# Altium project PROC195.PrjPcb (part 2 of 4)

## Sheet PROC195_EPWM.SchDoc
size 431 x 279 mm; Date: Not shown in title block; ApprovedBy: Not shown in title block; CheckedBy: Not shown in title block; Author: Not shown in title block; CompanyName: Not shown in title block; Engineer: Not shown in title block; Organization: Not shown in title block; Address1: Not shown in title block; Address2: Not shown in title block; Address3: Not shown in title block; Address4: Not shown in title block; DocumentNumber: 1; Revision: Use project parameter SCH_Rev; SheetNumber: 10; SheetTotal: 20; PageSetup: Record=PageOptions¦CenterHorizontal=True¦CenterVertical=True¦PrintScale=0.97¦XCorrection=1.00¦YCorrection=1.00¦PrintKind=0¦BorderSize=5000000¦LeftOffset=0¦BottomOffset=0¦Orientation=2¦PaperLength=1000¦PaperWidth=1000¦Scale=100¦PaperSource=15¦PrintQuality=600¦MediaType=1¦DitherType=10¦PaperKind=Letter¦PrintScaleMode=1
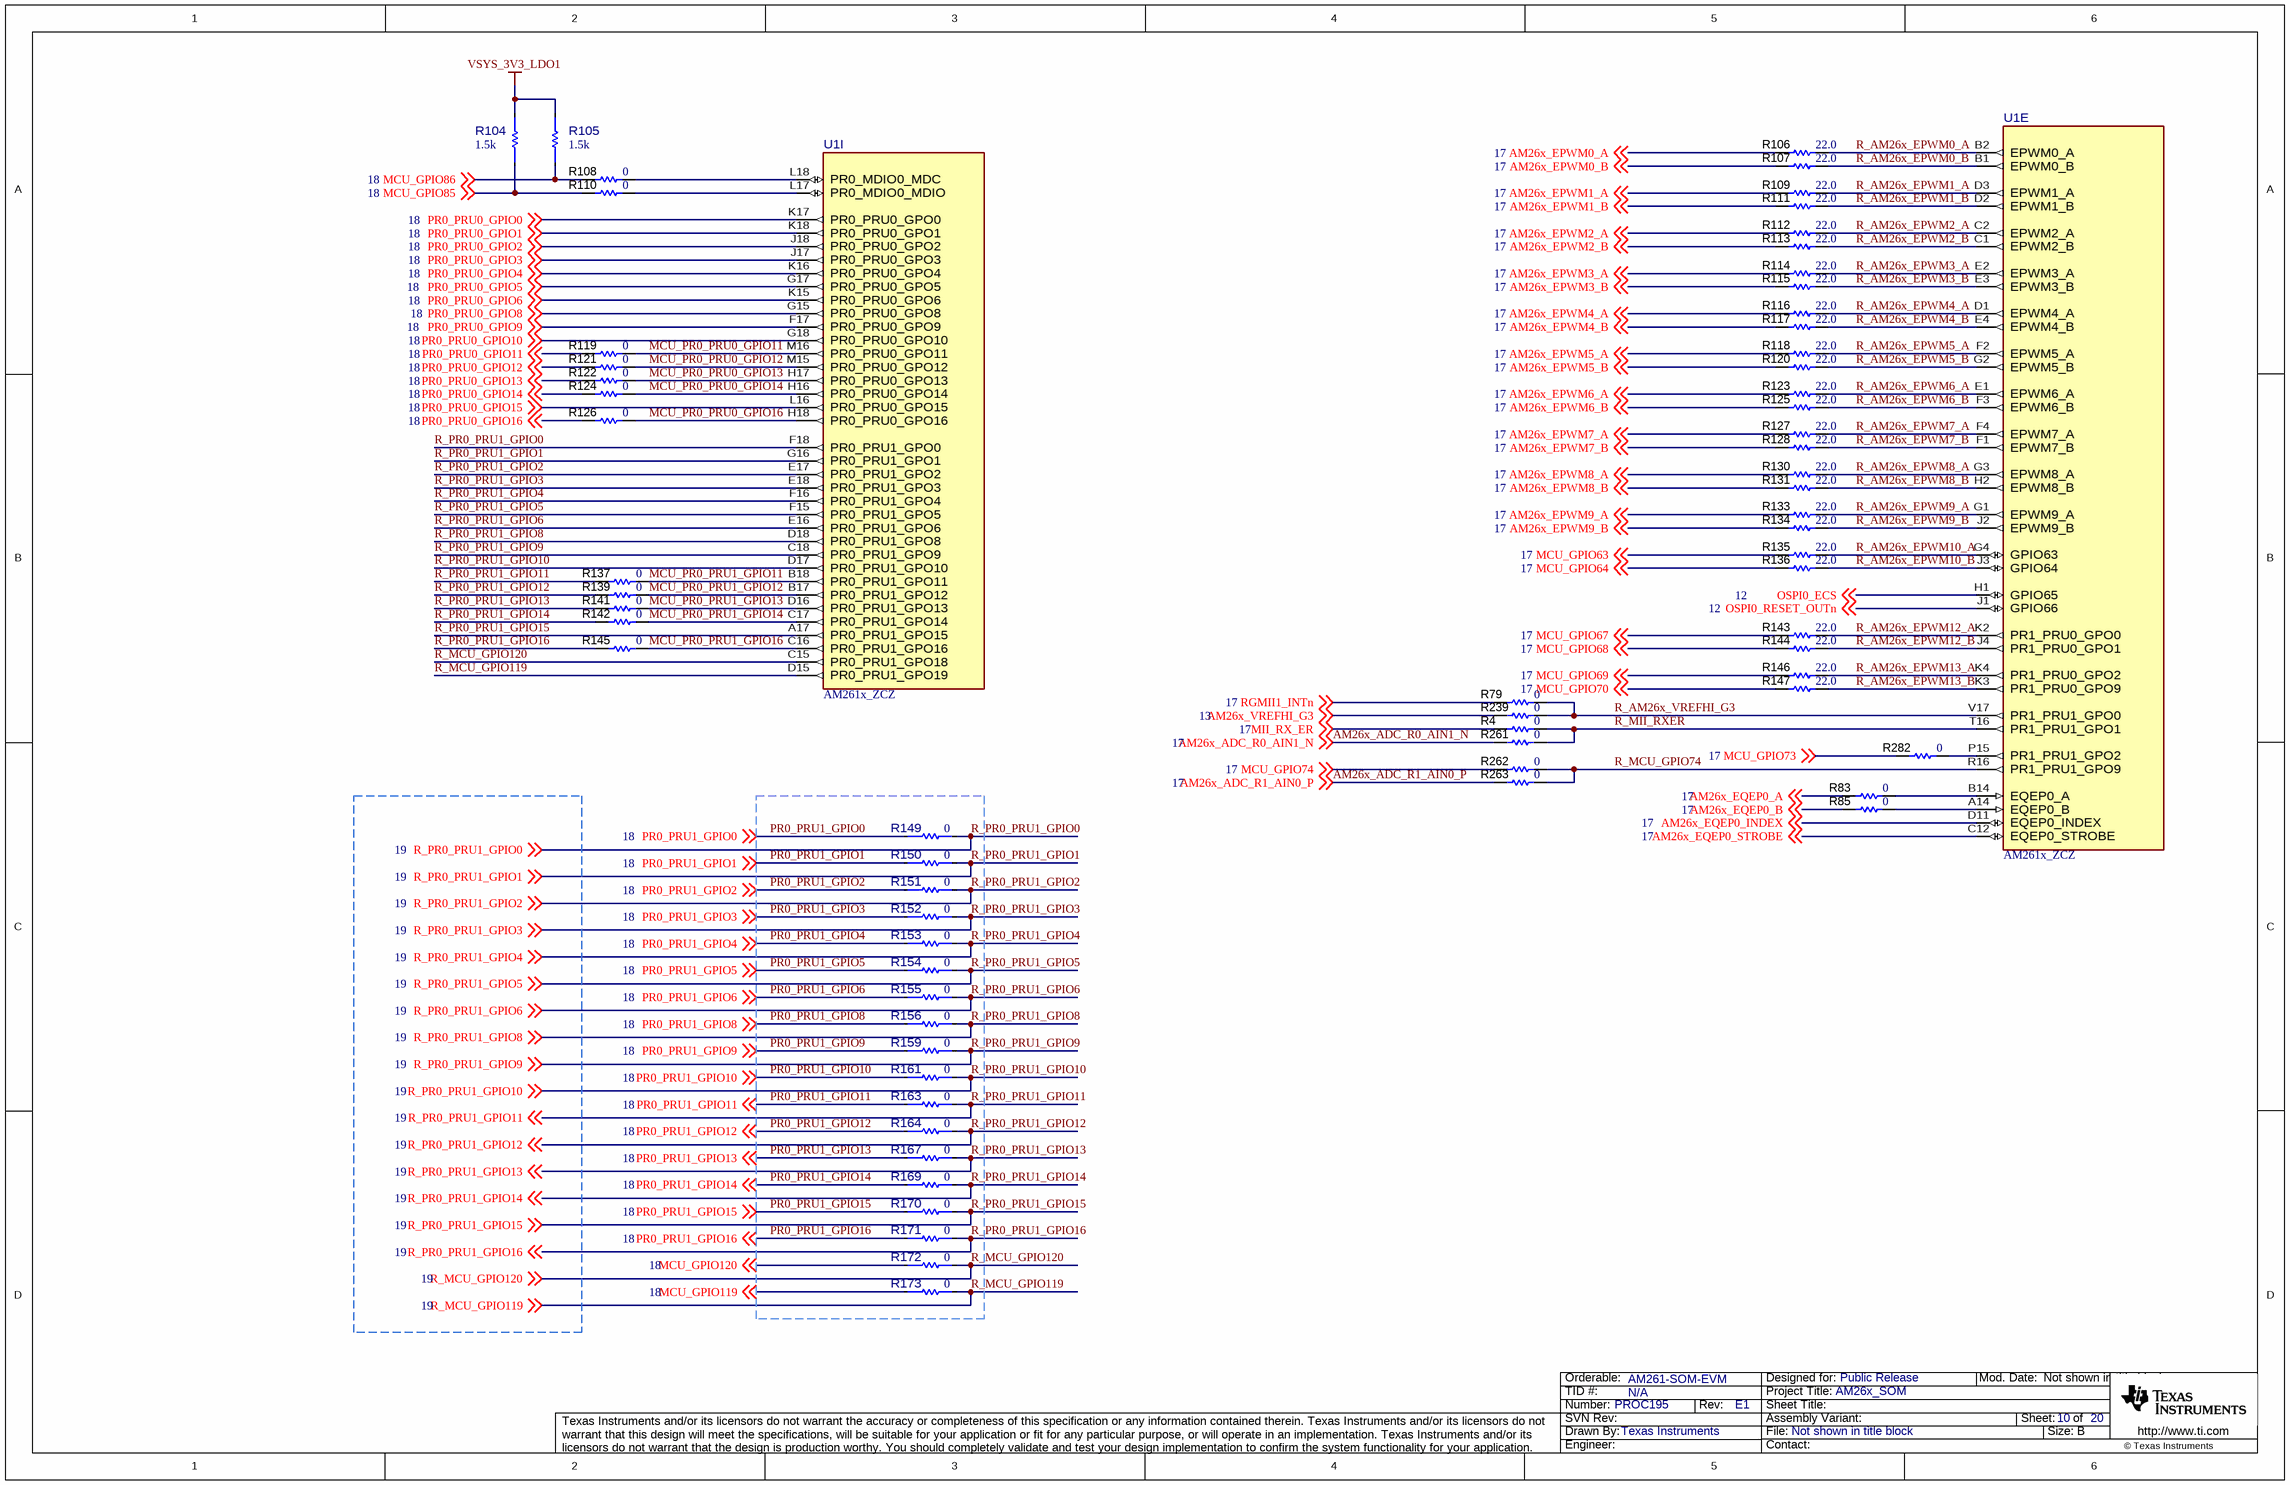
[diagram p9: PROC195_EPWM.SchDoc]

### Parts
R4  ValueDisplayed: 0  [0201]  (hidden comment: ERJ-1GN0R00C)
R79  ValueDisplayed: 0  [0201]  (hidden comment: ERJ-1GN0R00C)
R83  ValueDisplayed: 0  [0201]  (hidden comment: ERJ-1GN0R00C)
R85  ValueDisplayed: 0  [0201]  (hidden comment: ERJ-1GN0R00C)
R104  value 1.5k  [FP-ERJ-2GEJ152X_0402-MFG]  (hidden comment: ERJ-2GEJ152X)
R105  value 1.5k  [FP-ERJ-2GEJ152X_0402-MFG]  (hidden comment: ERJ-2GEJ152X)
R106  ValueDisplayed: 22.0  [0201]  (hidden comment: RC0201FR-0722RL)
R107  ValueDisplayed: 22.0  [0201]  (hidden comment: RC0201FR-0722RL)
R108  ValueDisplayed: 0  [0201]  (hidden comment: ERJ-1GN0R00C)
R109  ValueDisplayed: 22.0  [0201]  (hidden comment: RC0201FR-0722RL)
R110  ValueDisplayed: 0  [0201]  (hidden comment: ERJ-1GN0R00C)
R111  ValueDisplayed: 22.0  [0201]  (hidden comment: RC0201FR-0722RL)
R112  ValueDisplayed: 22.0  [0201]  (hidden comment: RC0201FR-0722RL)
R113  ValueDisplayed: 22.0  [0201]  (hidden comment: RC0201FR-0722RL)
R114  ValueDisplayed: 22.0  [0201]  (hidden comment: RC0201FR-0722RL)
R115  ValueDisplayed: 22.0  [0201]  (hidden comment: RC0201FR-0722RL)
R116  ValueDisplayed: 22.0  [0201]  (hidden comment: RC0201FR-0722RL)
R117  ValueDisplayed: 22.0  [0201]  (hidden comment: RC0201FR-0722RL)
R118  ValueDisplayed: 22.0  [0201]  (hidden comment: RC0201FR-0722RL)
R119  ValueDisplayed: 0  [0201]  (hidden comment: ERJ-1GN0R00C)
R120  ValueDisplayed: 22.0  [0201]  (hidden comment: RC0201FR-0722RL)
R121  ValueDisplayed: 0  [0201]  (hidden comment: ERJ-1GN0R00C)
R122  ValueDisplayed: 0  [0201]  (hidden comment: ERJ-1GN0R00C)
R123  ValueDisplayed: 22.0  [0201]  (hidden comment: RC0201FR-0722RL)
R124  ValueDisplayed: 0  [0201]  (hidden comment: ERJ-1GN0R00C)
R125  ValueDisplayed: 22.0  [0201]  (hidden comment: RC0201FR-0722RL)
R126  ValueDisplayed: 0  [0201]  (hidden comment: ERJ-1GN0R00C)
R127  ValueDisplayed: 22.0  [0201]  (hidden comment: RC0201FR-0722RL)
R128  ValueDisplayed: 22.0  [0201]  (hidden comment: RC0201FR-0722RL)
R130  ValueDisplayed: 22.0  [0201]  (hidden comment: RC0201FR-0722RL)
R131  ValueDisplayed: 22.0  [0201]  (hidden comment: RC0201FR-0722RL)
R133  ValueDisplayed: 22.0  [0201]  (hidden comment: RC0201FR-0722RL)
R134  ValueDisplayed: 22.0  [0201]  (hidden comment: RC0201FR-0722RL)
R135  ValueDisplayed: 22.0  [0201]  (hidden comment: RC0201FR-0722RL)
R136  ValueDisplayed: 22.0  [0201]  (hidden comment: RC0201FR-0722RL)
R137  ValueDisplayed: 0  [0201]  (hidden comment: ERJ-1GN0R00C)
R139  ValueDisplayed: 0  [0201]  (hidden comment: ERJ-1GN0R00C)
R141  ValueDisplayed: 0  [0201]  (hidden comment: ERJ-1GN0R00C)
R142  ValueDisplayed: 0  [0201]  (hidden comment: ERJ-1GN0R00C)
R143  ValueDisplayed: 22.0  [0201]  (hidden comment: RC0201FR-0722RL)
R144  ValueDisplayed: 22.0  [0201]  (hidden comment: RC0201FR-0722RL)
R145  ValueDisplayed: 0  [0201]  (hidden comment: ERJ-1GN0R00C)
R146  ValueDisplayed: 22.0  [0201]  (hidden comment: RC0201FR-0722RL)
R147  ValueDisplayed: 22.0  [0201]  (hidden comment: RC0201FR-0722RL)
R149  value 0  [FP-ERJ-2GE0R00X_0402-MFG]  (hidden comment: ERJ-2GE0R00X)
R150  value 0  [FP-ERJ-2GE0R00X_0402-MFG]  (hidden comment: ERJ-2GE0R00X)
R151  value 0  [FP-ERJ-2GE0R00X_0402-MFG]  (hidden comment: ERJ-2GE0R00X)
R152  value 0  [FP-ERJ-2GE0R00X_0402-MFG]  (hidden comment: ERJ-2GE0R00X)
R153  value 0  [FP-ERJ-2GE0R00X_0402-MFG]  (hidden comment: ERJ-2GE0R00X)
R154  value 0  [FP-ERJ-2GE0R00X_0402-MFG]  (hidden comment: ERJ-2GE0R00X)
R155  value 0  [FP-ERJ-2GE0R00X_0402-MFG]  (hidden comment: ERJ-2GE0R00X)
R156  value 0  [FP-ERJ-2GE0R00X_0402-MFG]  (hidden comment: ERJ-2GE0R00X)
R159  value 0  [FP-ERJ-2GE0R00X_0402-MFG]  (hidden comment: ERJ-2GE0R00X)
R161  value 0  [FP-ERJ-2GE0R00X_0402-MFG]  (hidden comment: ERJ-2GE0R00X)
R163  value 0  [FP-ERJ-2GE0R00X_0402-MFG]  (hidden comment: ERJ-2GE0R00X)
R164  value 0  [FP-ERJ-2GE0R00X_0402-MFG]  (hidden comment: ERJ-2GE0R00X)
R167  value 0  [FP-ERJ-2GE0R00X_0402-MFG]  (hidden comment: ERJ-2GE0R00X)
R169  value 0  [FP-ERJ-2GE0R00X_0402-MFG]  (hidden comment: ERJ-2GE0R00X)
R170  value 0  [FP-ERJ-2GE0R00X_0402-MFG]  (hidden comment: ERJ-2GE0R00X)
R171  value 0  [FP-ERJ-2GE0R00X_0402-MFG]  (hidden comment: ERJ-2GE0R00X)
R172  value 0  [FP-ERJ-2GE0R00X_0402-MFG]  (hidden comment: ERJ-2GE0R00X)
R173  value 0  [FP-ERJ-2GE0R00X_0402-MFG]  (hidden comment: ERJ-2GE0R00X)
R239  ValueDisplayed: 0  [0201]  (hidden comment: ERJ-1GN0R00C)
R261  ValueDisplayed: 0  [0201]  (hidden comment: ERJ-1GN0R00C)
R262  ValueDisplayed: 0  [0201]  (hidden comment: ERJ-1GN0R00C)
R263  ValueDisplayed: 0  [0201]  (hidden comment: ERJ-1GN0R00C)
R282  ValueDisplayed: 0  [0201]  (hidden comment: ERJ-1GN0R00C)
U1  AM261x_ZCZ  [ZCZ0324A-MFG]  (parts E,I of 13)

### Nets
VSYS_3V3_LDO1: R104.2 R105.2
AM26x_ADC_R0_AIN1_N: R261.1 ; off-sheet AM26x_ADC_R0_AIN1_N
AM26x_ADC_R1_AIN0_P: R263.1 ; off-sheet AM26x_ADC_R1_AIN0_P
AM26x_EPWM0_A: R106.1 ; off-sheet AM26x_EPWM0_A
AM26x_EPWM0_B: R107.1 ; off-sheet AM26x_EPWM0_B
AM26x_EPWM1_A: R109.1 ; off-sheet AM26x_EPWM1_A
AM26x_EPWM1_B: R111.1 ; off-sheet AM26x_EPWM1_B
AM26x_EPWM2_A: R112.1 ; off-sheet AM26x_EPWM2_A
AM26x_EPWM2_B: R113.1 ; off-sheet AM26x_EPWM2_B
AM26x_EPWM3_A: R114.1 ; off-sheet AM26x_EPWM3_A
AM26x_EPWM3_B: R115.1 ; off-sheet AM26x_EPWM3_B
AM26x_EPWM4_A: R116.1 ; off-sheet AM26x_EPWM4_A
AM26x_EPWM4_B: R117.1 ; off-sheet AM26x_EPWM4_B
AM26x_EPWM5_A: R118.1 ; off-sheet AM26x_EPWM5_A
AM26x_EPWM5_B: R120.1 ; off-sheet AM26x_EPWM5_B
AM26x_EPWM6_A: R123.1 ; off-sheet AM26x_EPWM6_A
AM26x_EPWM6_B: R125.1 ; off-sheet AM26x_EPWM6_B
AM26x_EPWM7_A: R127.1 ; off-sheet AM26x_EPWM7_A
AM26x_EPWM7_B: R128.1 ; off-sheet AM26x_EPWM7_B
AM26x_EPWM8_A: R130.1 ; off-sheet AM26x_EPWM8_A
AM26x_EPWM8_B: R131.1 ; off-sheet AM26x_EPWM8_B
AM26x_EPWM9_A: R133.1 ; off-sheet AM26x_EPWM9_A
AM26x_EPWM9_B: R134.1 ; off-sheet AM26x_EPWM9_B
AM26x_EQEP0_A: R83.1 ; off-sheet AM26x_EQEP0_A
AM26x_EQEP0_B: R85.1 ; off-sheet AM26x_EQEP0_B
AM26x_EQEP0_INDEX: U1.D11(EQEP0_INDEX) ; off-sheet AM26x_EQEP0_INDEX
AM26x_EQEP0_STROBE: U1.C12(EQEP0_STROBE) ; off-sheet AM26x_EQEP0_STROBE
AM26x_VREFHI_G3: R239.1 ; off-sheet AM26x_VREFHI_G3  [project net ADC_VREFHI_G2_G3]
MCU_GPIO63: R135.1 ; off-sheet MCU_GPIO63
MCU_GPIO64: R136.1 ; off-sheet MCU_GPIO64
MCU_GPIO67: R143.1 ; off-sheet MCU_GPIO67
MCU_GPIO68: R144.1 ; off-sheet MCU_GPIO68
MCU_GPIO69: R146.1 ; off-sheet MCU_GPIO69
MCU_GPIO70: R147.1 ; off-sheet MCU_GPIO70
MCU_GPIO73: R282.1 ; off-sheet MCU_GPIO73
MCU_GPIO74: R262.1 ; off-sheet MCU_GPIO74
MCU_GPIO85: R104.1 R110.1 ; off-sheet MCU_GPIO85
MCU_GPIO86: R105.1 R108.1 ; off-sheet MCU_GPIO86
MCU_GPIO119: R173.1 ; off-sheet MCU_GPIO119
MCU_GPIO120: R172.1 ; off-sheet MCU_GPIO120
MCU_PR0_PRU0_GPIO11: R119.2 U1.M16(PR0_PRU0_GPO11)
MCU_PR0_PRU0_GPIO12: R121.2 U1.M15(PR0_PRU0_GPO12)
MCU_PR0_PRU0_GPIO13: R122.2 U1.H17(PR0_PRU0_GPO13)
MCU_PR0_PRU0_GPIO14: R124.2 U1.H16(PR0_PRU0_GPO14)
MCU_PR0_PRU0_GPIO16: R126.2 U1.H18(PR0_PRU0_GPO16)
MCU_PR0_PRU1_GPIO11: R137.2 U1.B18(PR0_PRU1_GPO11)
MCU_PR0_PRU1_GPIO12: R139.2 U1.B17(PR0_PRU1_GPO12)
MCU_PR0_PRU1_GPIO13: R141.2 U1.D16(PR0_PRU1_GPO13)
MCU_PR0_PRU1_GPIO14: R142.2 U1.C17(PR0_PRU1_GPO14)
MCU_PR0_PRU1_GPIO16: R145.2 U1.C16(PR0_PRU1_GPO16)
MII_RX_ER: R4.1 ; off-sheet MII_RX_ER
OSPI0_ECS: U1.H1(GPIO65) ; off-sheet OSPI0_ECS
OSPI0_RESET_OUTn: U1.J1(GPIO66) ; off-sheet OSPI0_RESET_OUTn
PR0_PRU0_GPIO0: U1.K17(PR0_PRU0_GPO0) ; off-sheet PR0_PRU0_GPIO0
PR0_PRU0_GPIO1: U1.K18(PR0_PRU0_GPO1) ; off-sheet PR0_PRU0_GPIO1
PR0_PRU0_GPIO2: U1.J18(PR0_PRU0_GPO2) ; off-sheet PR0_PRU0_GPIO2
PR0_PRU0_GPIO3: U1.J17(PR0_PRU0_GPO3) ; off-sheet PR0_PRU0_GPIO3
PR0_PRU0_GPIO4: U1.K16(PR0_PRU0_GPO4) ; off-sheet PR0_PRU0_GPIO4
PR0_PRU0_GPIO5: U1.G17(PR0_PRU0_GPO5) ; off-sheet PR0_PRU0_GPIO5
PR0_PRU0_GPIO6: U1.K15(PR0_PRU0_GPO6) ; off-sheet PR0_PRU0_GPIO6
PR0_PRU0_GPIO8: U1.G15(PR0_PRU0_GPO8) ; off-sheet PR0_PRU0_GPIO8
PR0_PRU0_GPIO9: U1.F17(PR0_PRU0_GPO9) ; off-sheet PR0_PRU0_GPIO9
PR0_PRU0_GPIO10: U1.G18(PR0_PRU0_GPO10) ; off-sheet PR0_PRU0_GPIO10
PR0_PRU0_GPIO11: R119.1 ; off-sheet PR0_PRU0_GPIO11
PR0_PRU0_GPIO12: R121.1 ; off-sheet PR0_PRU0_GPIO12
PR0_PRU0_GPIO13: R122.1 ; off-sheet PR0_PRU0_GPIO13
PR0_PRU0_GPIO14: R124.1 ; off-sheet PR0_PRU0_GPIO14
PR0_PRU0_GPIO15: U1.L16(PR0_PRU0_GPO15) ; off-sheet PR0_PRU0_GPIO15
PR0_PRU0_GPIO16: R126.1 ; off-sheet PR0_PRU0_GPIO16
PR0_PRU1_GPIO0: R149.1 ; off-sheet PR0_PRU1_GPIO0
PR0_PRU1_GPIO1: R150.1 ; off-sheet PR0_PRU1_GPIO1
PR0_PRU1_GPIO2: R151.1 ; off-sheet PR0_PRU1_GPIO2
PR0_PRU1_GPIO3: R152.1 ; off-sheet PR0_PRU1_GPIO3
PR0_PRU1_GPIO4: R153.1 ; off-sheet PR0_PRU1_GPIO4
PR0_PRU1_GPIO5: R154.1 ; off-sheet PR0_PRU1_GPIO5
PR0_PRU1_GPIO6: R155.1 ; off-sheet PR0_PRU1_GPIO6
PR0_PRU1_GPIO8: R156.1 ; off-sheet PR0_PRU1_GPIO8
PR0_PRU1_GPIO9: R159.1 ; off-sheet PR0_PRU1_GPIO9
PR0_PRU1_GPIO10: R161.1 ; off-sheet PR0_PRU1_GPIO10
PR0_PRU1_GPIO11: R163.1 ; off-sheet PR0_PRU1_GPIO11
PR0_PRU1_GPIO12: R164.1 ; off-sheet PR0_PRU1_GPIO12
PR0_PRU1_GPIO13: R167.1 ; off-sheet PR0_PRU1_GPIO13
PR0_PRU1_GPIO14: R169.1 ; off-sheet PR0_PRU1_GPIO14
PR0_PRU1_GPIO15: R170.1 ; off-sheet PR0_PRU1_GPIO15
PR0_PRU1_GPIO16: R171.1 ; off-sheet PR0_PRU1_GPIO16
R_AM26x_EPWM0_A: R106.2 U1.B2(EPWM0_A)
R_AM26x_EPWM0_B: R107.2 U1.B1(EPWM0_B)
R_AM26x_EPWM1_A: R109.2 U1.D3(EPWM1_A)
R_AM26x_EPWM1_B: R111.2 U1.D2(EPWM1_B)
R_AM26x_EPWM2_A: R112.2 U1.C2(EPWM2_A)
R_AM26x_EPWM2_B: R113.2 U1.C1(EPWM2_B)
R_AM26x_EPWM3_A: R114.2 U1.E2(EPWM3_A)
R_AM26x_EPWM3_B: R115.2 U1.E3(EPWM3_B)
R_AM26x_EPWM4_A: R116.2 U1.D1(EPWM4_A)
R_AM26x_EPWM4_B: R117.2 U1.E4(EPWM4_B)
R_AM26x_EPWM5_A: R118.2 U1.F2(EPWM5_A)
R_AM26x_EPWM5_B: R120.2 U1.G2(EPWM5_B)
R_AM26x_EPWM6_A: R123.2 U1.E1(EPWM6_A)
R_AM26x_EPWM6_B: R125.2 U1.F3(EPWM6_B)
R_AM26x_EPWM7_A: R127.2 U1.F4(EPWM7_A)
R_AM26x_EPWM7_B: R128.2 U1.F1(EPWM7_B)
R_AM26x_EPWM8_A: R130.2 U1.G3(EPWM8_A)
R_AM26x_EPWM8_B: R131.2 U1.H2(EPWM8_B)
R_AM26x_EPWM9_A: R133.2 U1.G1(EPWM9_A)
R_AM26x_EPWM9_B: R134.2 U1.J2(EPWM9_B)
R_AM26x_EPWM10_A: R135.2 U1.G4(GPIO63)
R_AM26x_EPWM10_B: R136.2 U1.J3(GPIO64)
R_AM26x_EPWM12_A: R143.2 U1.K2(PR1_PRU0_GPO0)
R_AM26x_EPWM12_B: R144.2 U1.J4(PR1_PRU0_GPO1)
R_AM26x_EPWM13_A: R146.2 U1.K4(PR1_PRU0_GPO2)
R_AM26x_EPWM13_B: R147.2 U1.K3(PR1_PRU0_GPO9)
R_AM26x_VREFHI_G3: R79.2 R239.2 U1.V17(PR1_PRU1_GPO0)
R_MCU_GPIO74: R262.2 R263.2 U1.R16(PR1_PRU1_GPO9)
R_MCU_GPIO119: R173.2 U1.D15(PR0_PRU1_GPO19) ; off-sheet R_MCU_GPIO119
R_MCU_GPIO120: R172.2 U1.C15(PR0_PRU1_GPO18) ; off-sheet R_MCU_GPIO120
R_MII_RXER: R4.2 R261.2 U1.T16(PR1_PRU1_GPO1)
R_PR0_PRU1_GPIO0: R149.2 U1.F18(PR0_PRU1_GPO0) ; off-sheet R_PR0_PRU1_GPIO0
R_PR0_PRU1_GPIO1: R150.2 U1.G16(PR0_PRU1_GPO1) ; off-sheet R_PR0_PRU1_GPIO1
R_PR0_PRU1_GPIO2: R151.2 U1.E17(PR0_PRU1_GPO2) ; off-sheet R_PR0_PRU1_GPIO2
R_PR0_PRU1_GPIO3: R152.2 U1.E18(PR0_PRU1_GPO3) ; off-sheet R_PR0_PRU1_GPIO3
R_PR0_PRU1_GPIO4: R153.2 U1.F16(PR0_PRU1_GPO4) ; off-sheet R_PR0_PRU1_GPIO4
R_PR0_PRU1_GPIO5: R154.2 U1.F15(PR0_PRU1_GPO5) ; off-sheet R_PR0_PRU1_GPIO5
R_PR0_PRU1_GPIO6: R155.2 U1.E16(PR0_PRU1_GPO6) ; off-sheet R_PR0_PRU1_GPIO6
R_PR0_PRU1_GPIO8: R156.2 U1.D18(PR0_PRU1_GPO8) ; off-sheet R_PR0_PRU1_GPIO8
R_PR0_PRU1_GPIO9: R159.2 U1.C18(PR0_PRU1_GPO9) ; off-sheet R_PR0_PRU1_GPIO9
R_PR0_PRU1_GPIO10: R161.2 U1.D17(PR0_PRU1_GPO10) ; off-sheet R_PR0_PRU1_GPIO10
R_PR0_PRU1_GPIO11: R137.1 R163.2 ; off-sheet R_PR0_PRU1_GPIO11
R_PR0_PRU1_GPIO12: R139.1 R164.2 ; off-sheet R_PR0_PRU1_GPIO12
R_PR0_PRU1_GPIO13: R141.1 R167.2 ; off-sheet R_PR0_PRU1_GPIO13
R_PR0_PRU1_GPIO14: R142.1 R169.2 ; off-sheet R_PR0_PRU1_GPIO14
R_PR0_PRU1_GPIO15: R170.2 U1.A17(PR0_PRU1_GPO15) ; off-sheet R_PR0_PRU1_GPIO15
R_PR0_PRU1_GPIO16: R145.1 R171.2 ; off-sheet R_PR0_PRU1_GPIO16
RGMII1_INTn: R79.1 ; off-sheet RGMII1_INTn
NetR83_2: R83.2 U1.B14(EQEP0_A)
NetR85_2: R85.2 U1.A14(EQEP0_B)
NetR108_2: R108.2 U1.L18(PR0_MDIO0_MDC)
NetR110_2: R110.2 U1.L17(PR0_MDIO0_MDIO)
NetR282_2: R282.2 U1.P15(PR1_PRU1_GPO2)

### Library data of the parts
R4 R79 R83 R85 R108 R110 R119 R121 R122 R124 R126 R137 R139 R141 R142 R145 R239 R261-R263 R282 = CMP-0065361-1: RES, 0, 5%, .05 W, AEC-Q200 Grade 0, 0201; Manufacturer: Panasonic; Power_W: 50mW; Green_Lifecycle: Not Set; TempCo: ppm/C; Value_Code: 0000; Green_REACh: Incomplete; U/M: EA; Value: 0; EIA_Code: E24; SizeX_mm: 0.6; SizeY_mm: 0.3; SizeZ_mm: 0.26; Value2: .05W; SizeArea_mm2: 0.18; AEC Qualified: Y; AEC Category: Q200
R104 R105 = CMP-0042990-1: Res Thick Film 0402 1.5K Ohm 5% 1/10W ±200ppm/°C Molded SMD Punched Carrier T/R; Manufacturer: Panasonic; AEC Grade: Grade 0; AEC Qualified: Yes; Power_W: 100mW; SizeZ_mm: 0.4mm; VDC_V: 50V; Category 5A00970A6D5C81C7: Uncategorized; Category 5C6A91606D4187Ad: Resistors; Category 7542B8484461Ae85: Passive Components; Category Cd01000Bfc2916C6: Single Components
R106 R107 R109 R111-R118 R120 R123 R125 R127 R128 R130 R131 R133-R136 R143 R144 R146 R147 = CMP-0027500-1: RES, 22.0, 1%, 0.05 W, 0201; Manufacturer: Yageo America; Power_W: 50mW; TempCo: 200 ppm/C; Value_Code: 22R0; U/M: EA; Value: 22.0; Res_ohm: 22; SizeX_mm: 0.6; SizeY_mm: 0.3; SizeZ_mm: 0.26; Value2: 0.05W; SizeArea_mm2: 0.18; AEC Qualified: N; VDC_V: 25V; AEC Category: Q200
R149-R156 R159 R161 R163 R164 R167 R169-R173 = CMP-0002710-1: 0 Ohms Jumper Chip Resistor 0402 (1005 Metric) Automotive AEC-Q200 Thick Film; Manufacturer: Panasonic; SizeZ_mm: 0.4mm; AEC Qualified: Yes; AEC Grade: Grade 0; Power: 100mW
U1 = CMP-0121930-1: Manufacturer: Texas Instruments; SizeZ_mm: 1.4mm; Standoff Height: 0.35mm

## Sheet PROC195_SDFM, JTAG.SchDoc
size 431 x 279 mm; Date: Not shown in title block; ApprovedBy: Not shown in title block; CheckedBy: Not shown in title block; Author: Not shown in title block; CompanyName: Not shown in title block; Engineer: Not shown in title block; Organization: Not shown in title block; Address1: Not shown in title block; Address2: Not shown in title block; Address3: Not shown in title block; Address4: Not shown in title block; DocumentNumber: 1; Revision: Use project parameter SCH_Rev; SheetNumber: 11; SheetTotal: 20; PageSetup: Record=PageOptions¦CenterHorizontal=True¦CenterVertical=True¦PrintScale=1.00¦XCorrection=1.00¦YCorrection=1.00¦PrintKind=0¦BorderSize=5000000¦LeftOffset=0¦BottomOffset=0¦Orientation=2¦PaperLength=1000¦PaperWidth=1000¦Scale=100¦PaperSource=15¦PrintQuality=600¦MediaType=1¦DitherType=10¦PaperKind=Letter¦PrintScaleMode=1
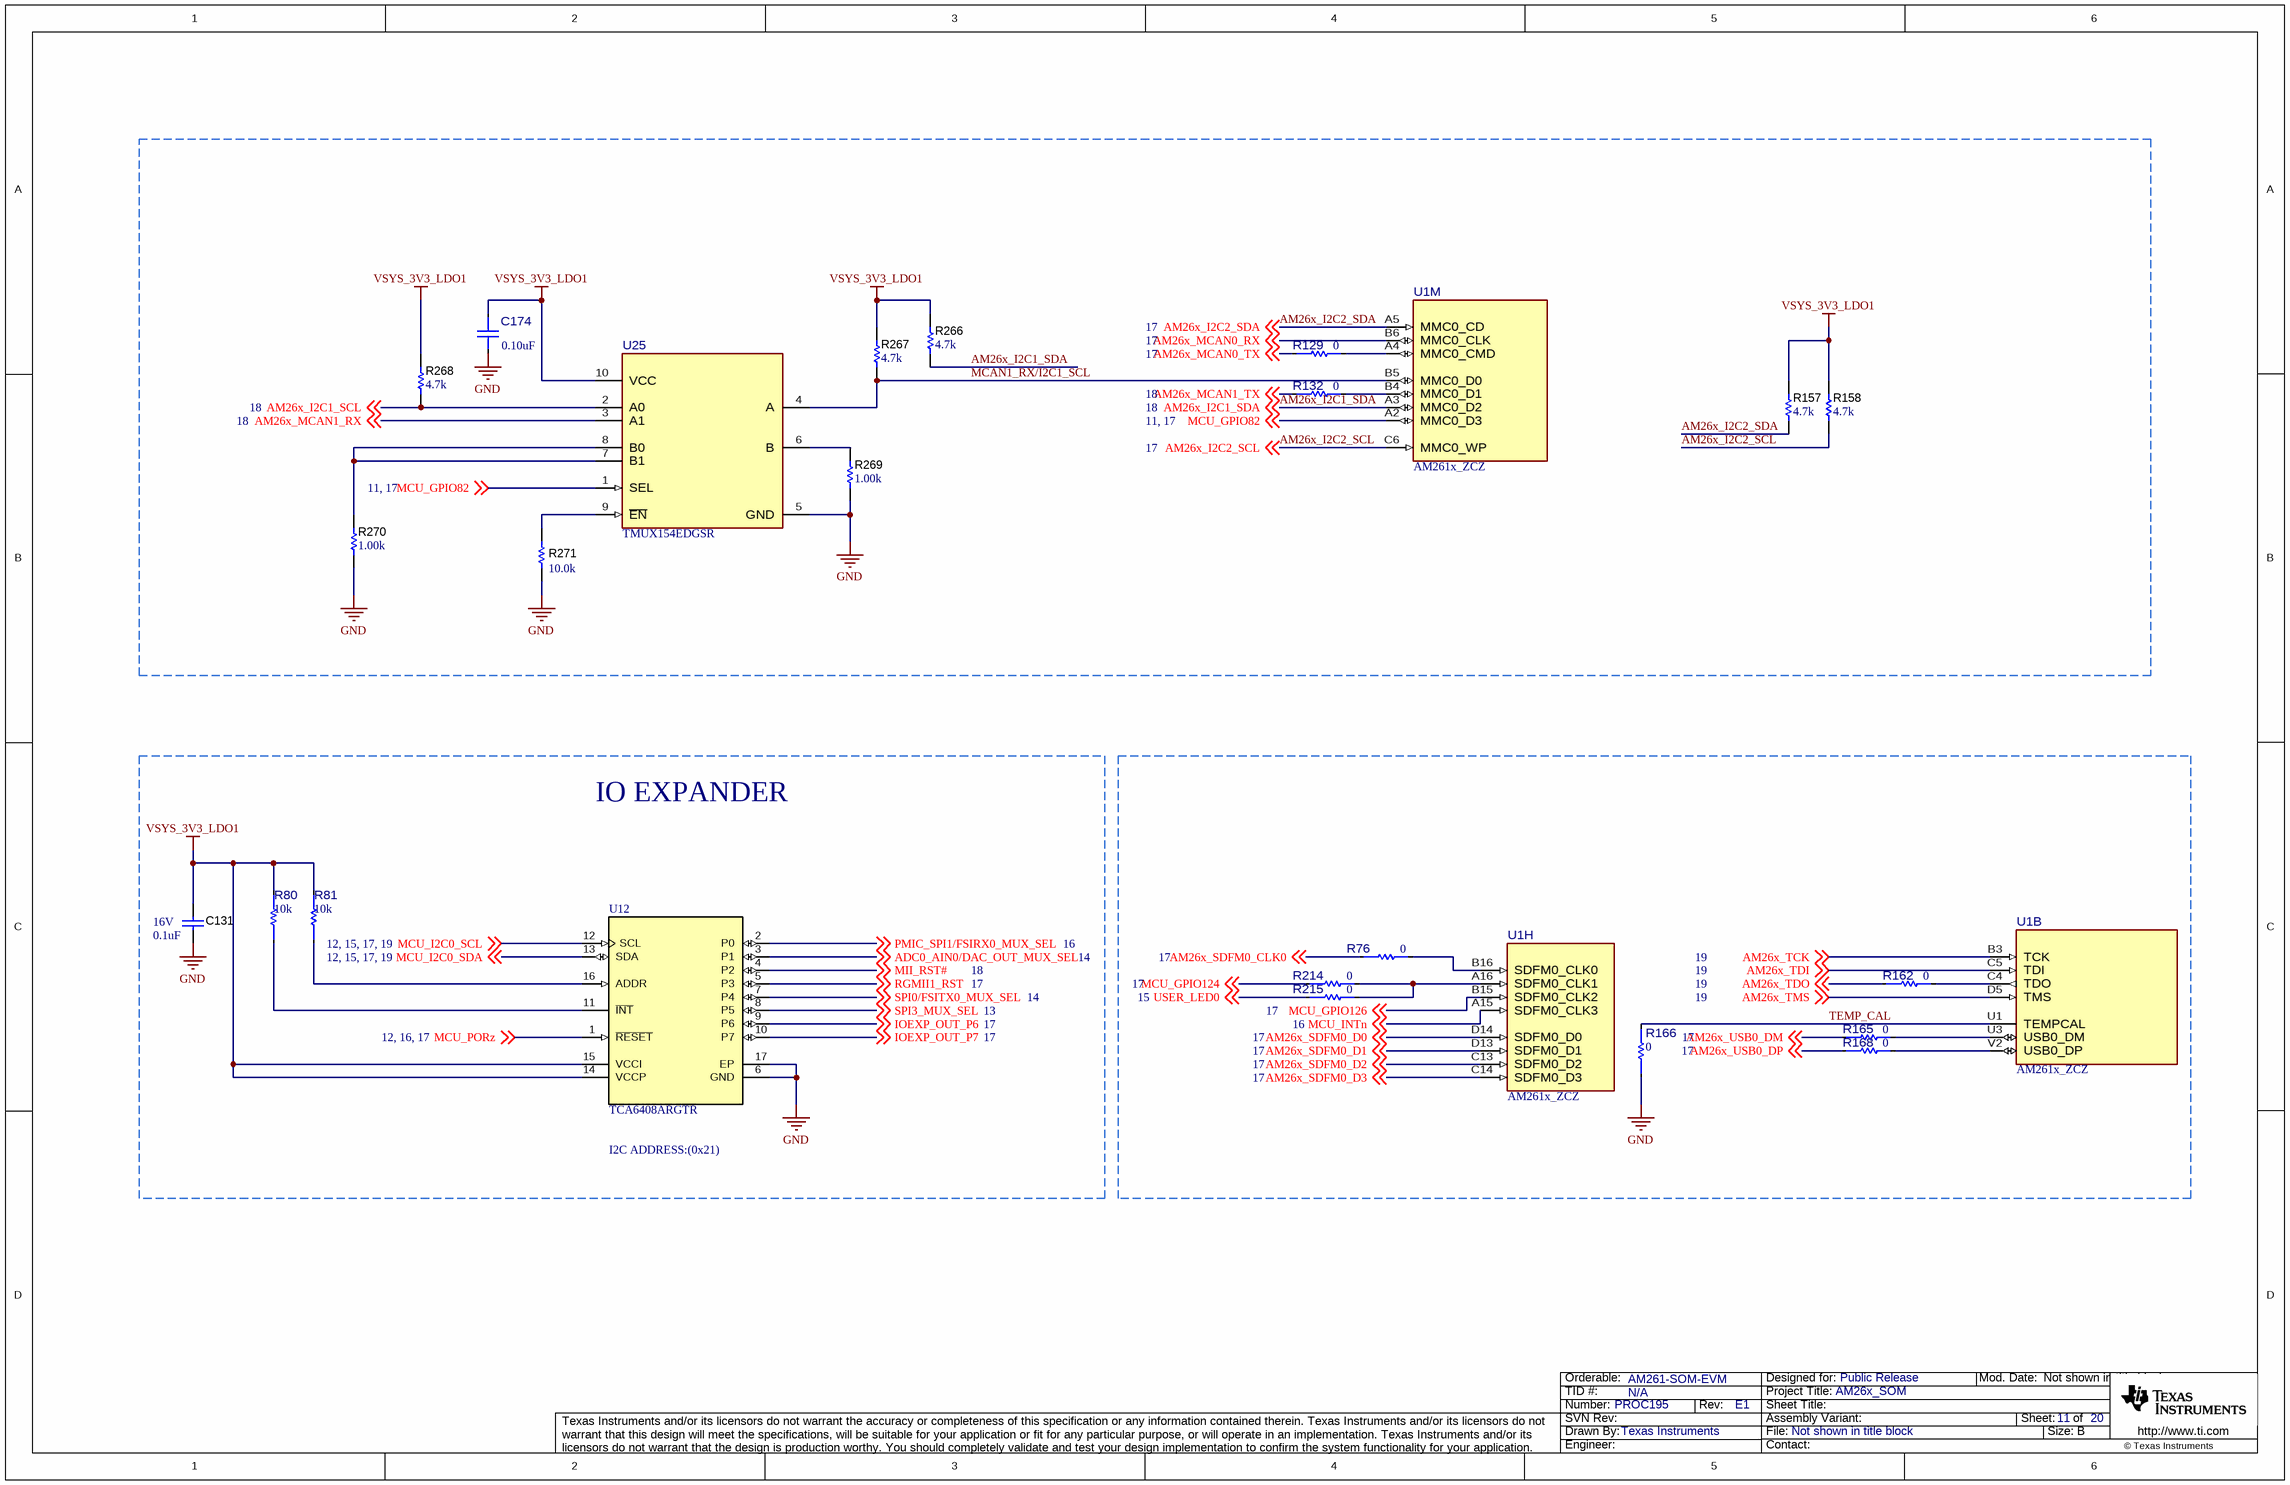
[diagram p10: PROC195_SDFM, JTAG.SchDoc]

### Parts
C131  VDC_V: 16V  ValueDisplayed: 0.1uF  [0201]  (hidden comment: GRM033Z71C104KE14D)
C174  ValueDisplayed: 0.10uF  [FP-GRM155R71H104KE14D_0402-MFG]  (hidden comment: GRM155R71H104KE14D)
R76  value 0  [FP-ERJ-2GE0R00X_0402-MFG]  (hidden comment: ERJ-2GE0R00X)
R80  value 10k  [FP-RC0402JR-0710KL_0402-MFG]  (hidden comment: RC0402JR-0710KL)
R81  value 10k  [FP-RC0402JR-0710KL_0402-MFG]  (hidden comment: RC0402JR-0710KL)
R129  value 0  [FP-ERJ-2GE0R00X_0402-MFG]  (hidden comment: ERJ-2GE0R00X)
R132  value 0  [FP-ERJ-2GE0R00X_0402-MFG]  (hidden comment: ERJ-2GE0R00X)
R157  ValueDisplayed: 4.7k  [0402]  (hidden comment: CRCW04024K70JNED)
R158  ValueDisplayed: 4.7k  [0402]  (hidden comment: CRCW04024K70JNED)
R162  value 0  [FP-ERJ-2GE0R00X_0402-MFG]  (hidden comment: ERJ-2GE0R00X)
R165  value 0  [FP-ERJ-2GE0R00X_0402-MFG]  (hidden comment: ERJ-2GE0R00X)
R166  value 0  [FP-ERJ-2GE0R00X_0402-MFG]  (hidden comment: ERJ-2GE0R00X)
R168  value 0  [FP-ERJ-2GE0R00X_0402-MFG]  (hidden comment: ERJ-2GE0R00X)
R214  value 0  [FP-ERJ-2GE0R00X_0402-MFG]  (hidden comment: ERJ-2GE0R00X)
R215  value 0  [FP-ERJ-2GE0R00X_0402-MFG]  (hidden comment: ERJ-2GE0R00X)
R266  ValueDisplayed: 4.7k  [0402]  (hidden comment: CRCW04024K70JNED)
R267  ValueDisplayed: 4.7k  [0402]  (hidden comment: CRCW04024K70JNED)
R268  ValueDisplayed: 4.7k  [0402]  (hidden comment: CRCW04024K70JNED)
R269  ValueDisplayed: 1.00k  [0402]  (hidden comment: ERJ-2RKF1001X)
R270  ValueDisplayed: 1.00k  [0402]  (hidden comment: ERJ-2RKF1001X)
R271  value 10.0k  [0402]  (hidden comment: AC0402FR-0710KL)
U1  AM261x_ZCZ  [ZCZ0324A-MFG]  (parts B,H,M of 13)
U12  TCA6408ARGTR  [RGT0016A]
U25  TMUX154EDGSR  [DGS0010A-MFG]

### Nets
GND: C131.2 C174.2 R166.1 R269.2 R270.2 R271.1 U12.6(GND) U12.17(EP) U25.5(GND)
VSYS_3V3_LDO1: C131.1 C174.1 R80.2 R81.2 R157.2 R158.2 R266.2 R267.2 R268.2 U12.14(VCCP) U12.15(VCCI) U25.10(VCC)
ADC0_AIN0/DAC_OUT_MUX_SEL: U12.3(P1) ; off-sheet ADC0_AIN0/DAC_OUT_MUX_SEL
AM26x_I2C1_SCL: R268.1 U25.2(A0) ; off-sheet AM26x_I2C1_SCL
AM26x_I2C1_SDA: R266.1 U1.A3(MMC0_D2) ; off-sheet AM26x_I2C1_SDA
AM26x_I2C2_SCL: R158.1 U1.C6(MMC0_WP) ; off-sheet AM26x_I2C2_SCL
AM26x_I2C2_SDA: R157.1 U1.A5(MMC0_CD) ; off-sheet AM26x_I2C2_SDA
AM26x_MCAN0_RX: U1.B6(MMC0_CLK) ; off-sheet AM26x_MCAN0_RX
AM26x_MCAN0_TX: R129.1 ; off-sheet AM26x_MCAN0_TX
AM26x_MCAN1_RX: U25.3(A1) ; off-sheet AM26x_MCAN1_RX
AM26x_MCAN1_TX: R132.1 ; off-sheet AM26x_MCAN1_TX
AM26x_SDFM0_CLK0: R76.1 ; off-sheet AM26x_SDFM0_CLK0
AM26x_SDFM0_D0: U1.D14(SDFM0_D0) ; off-sheet AM26x_SDFM0_D0
AM26x_SDFM0_D1: U1.D13(SDFM0_D1) ; off-sheet AM26x_SDFM0_D1
AM26x_SDFM0_D2: U1.C13(SDFM0_D2) ; off-sheet AM26x_SDFM0_D2
AM26x_SDFM0_D3: U1.C14(SDFM0_D3) ; off-sheet AM26x_SDFM0_D3
AM26x_TCK: U1.B3(TCK) ; off-sheet AM26x_TCK
AM26x_TDI: U1.C5(TDI) ; off-sheet AM26x_TDI
AM26x_TDO: R162.1 ; off-sheet AM26x_TDO
AM26x_TMS: U1.D5(TMS) ; off-sheet AM26x_TMS
AM26x_USB0_DM: R165.1 ; off-sheet AM26x_USB0_DM
AM26x_USB0_DP: R168.1 ; off-sheet AM26x_USB0_DP
IOEXP_OUT_P6: U12.9(P6) ; off-sheet IOEXP_OUT_P6
IOEXP_OUT_P7: U12.10(P7) ; off-sheet IOEXP_OUT_P7
MCAN1_RX/I2C1_SCL: R267.1 U1.B5(MMC0_D0) U25.4(A)
MCU_GPIO82: U1.A2(MMC0_D3) U25.1(SEL) ; off-sheet MCU_GPIO82
MCU_GPIO124: R214.1 ; off-sheet MCU_GPIO124
MCU_GPIO126: U1.B15(SDFM0_CLK2) ; off-sheet MCU_GPIO126
MCU_I2C0_SCL: U12.12(SCL) ; off-sheet MCU_I2C0_SCL
MCU_I2C0_SDA: U12.13(SDA) ; off-sheet MCU_I2C0_SDA
MCU_INTn: U1.A15(SDFM0_CLK3) ; off-sheet MCU_INTn
MCU_PORz: U12.1(~{RESET}) ; off-sheet MCU_PORz
MII_RST#: U12.4(P2) ; off-sheet MII_RST#
PMIC_SPI1/FSIRX0_MUX_SEL: U12.2(P0) ; off-sheet PMIC_SPI1/FSIRX0_MUX_SEL
RGMII1_RST: U12.5(P3) ; off-sheet RGMII1_RST
SPI0/FSITX0_MUX_SEL: U12.7(P4) ; off-sheet SPI0/FSITX0_MUX_SEL
SPI3_MUX_SEL: U12.8(P5) ; off-sheet SPI3_MUX_SEL
TEMP_CAL: R166.2 U1.U1(TEMPCAL)
USER_LED0: R215.1 ; off-sheet USER_LED0
NetR76_2: R76.2 U1.B16(SDFM0_CLK0)
NetR80_1: R80.1 U12.11(~{INT})
NetR81_1: R81.1 U12.16(ADDR)
NetR129_2: R129.2 U1.A4(MMC0_CMD)
NetR132_2: R132.2 U1.B4(MMC0_D1)
NetR162_2: R162.2 U1.C4(TDO)
NetR165_2: R165.2 U1.U3(USB0_DM)
NetR168_2: R168.2 U1.V2(USB0_DP)
NetR214_2: R214.2 R215.2 U1.A16(SDFM0_CLK1)
NetR269_1: R269.1 U25.6(B)
NetR270_1: R270.1 U25.7(B1) U25.8(B0)
NetR271_2: R271.2 U25.9(~{EN})

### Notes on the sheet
- IO EXPANDER
- I2C ADDRESS:(0x21)

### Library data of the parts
C131 = CMP-0064970-1: CAP, CERM, 0.1 uF, 16 V,+/- 10%, X7R, 0201; Manufacturer: MuRata; TaMin_C: -55°C; Polarized: N; SizeAreaWB_mm2: 2.08; Value1: Unknown; U/M: EA; Value: 0.1uF; TaMax_C: 125°C; SizeZ_mm: 0.26; SizeX_mm: 0.6; SizeY_mm: 0.3; SizeArea_mm2: 0.18; Cap_F: 100nF; AEC Category: Q200
C174 = CMP-0096855-1: Chip Multilayer Ceramic Capacitors for General Purpose, 0402, 0.10uF, X7R, 15%, 10%, 50V; Manufacturer: Murata; SizeZ_mm: 0.55mm; Value: 100nF; AEC Qualified: No
R76 R129 R132 R162 R165 R166 R168 R214 R215 = CMP-0002710-1: 0 Ohms Jumper Chip Resistor 0402 (1005 Metric) Automotive AEC-Q200 Thick Film; Manufacturer: Panasonic; AEC Grade: Grade 0; AEC Qualified: Yes; SizeZ_mm: 0.4mm; Power: 100mW
R80 R81 = CMP-0094798-1: Res Thick Film 0402 10K Ohm 5% 0.063W(1/16W) ±100ppm/C Pad SMD T/R; Manufacturer: YAGEO; Power_W: 63mW; TempCo: 100ppm/°C; SizeZ_mm: 0.4mm; AEC Qualified: No; VDC_V: 50V; Category Cd01000Bfc2916C6: Single Components; Category 5C6A91606D4187Ad: Resistors; Category 7542B8484461Ae85: Passive Components
R157 R158 R266-R268 = CMP-0026938-5: RES, 4.7 k, 5%, 0.063 W, AEC-Q200 Grade 0, 0402; Manufacturer: Vishay-Dale; Power_W: 63mW; TempCo: 200 ppm/C; Value_Code: 4k70; Value: 4.7k; EIA_Code: E24; SizeX_mm: 1; SizeY_mm: 0.5; SizeZ_mm: 0.6; Value2: 0.063W; AEC Qualified: Y; VDC_V: 50V; AEC Category: Q200; AEC Grade: 0
R269 R270 = CMP-0026657-1: RES, 1.00 k, 1%, 0.1 W, 0402; Manufacturer: Panasonic; Power_W: 100mW; TempCo: 100 ppm/C; Value_Code: 1k00; U/M: EA; Value: 1.00k; EIA_Code: E96; Res_ohm: 1k; SizeX_mm: 1; SizeY_mm: 0.5; SizeZ_mm: 0.6; Value2: 0.1W; VDC_V: 50V; AEC Category: Q200
R271 = CMP-0077731-1: RES, 10.0 k, 1%, 0.063 W, AEC-Q200 Grade 0, 0402; Manufacturer: Yageo America; Power_W: 63mW; TempCo: 100 ppm/C; Value_Code: 10k0; U/M: EA; EIA_Code: E96; Res_ohm: 10k; SizeX_mm: 1.0; SizeY_mm: 0.5; SizeZ_mm: 0.6; Value2: 0.063W; AEC Qualified: Y; VDC_V: 50V; AEC Grade: 0; AEC Category: Q200
U1 = CMP-0121930-1: as U1 on sheet PROC195_EPWM
U12 = CMP-0043157-2: Low-Voltage 8-Bit I2C and SMBus I/O Expander, 1.65 to 5.5 V, -40 to 85 degC, 16-pin QFN (RGT), Green (RoHS & no Sb/Br); Manufacturer: Texas Instruments; # of I/Os: 8; I2C Address: 0100 00x; Reset Input: Yes; Max Frequency(kHz): 400; VCC(Max)(V): 5.5; SubFamily: I2C IO Expander; VCC(Min)(V): 1.65
U25 = CMP-0122044-1: ESD-Protected, Low Capacitance, 2-Channel, 2:1 Switch, With Powered-off Protection; Manufacturer: Texas Instruments; SizeZ_mm: 1.1mm; AEC Qualified: No; -3Db Bandwith: 900MHz; Max Supply Voltage: 4.3V; Min Supply Voltage: 3V; Nominal Supply Current: 1uA; On State Resistance: 6Ω; PositionCount: 2; Standoff Height: 0.05mm; TaMax_C: +85°C; TaMin_C: -40°C

## Sheet PROC195_OSPI_BOOTMODE.SchDoc
size 431 x 279 mm; Date: Not shown in title block; ApprovedBy: Not shown in title block; CheckedBy: Not shown in title block; Author: Not shown in title block; CompanyName: Not shown in title block; Engineer: Not shown in title block; Organization: Not shown in title block; Address1: Not shown in title block; Address2: Not shown in title block; Address3: Not shown in title block; Address4: Not shown in title block; DocumentNumber: 1; Revision: Use project parameter SCH_Rev; SheetNumber: 12; SheetTotal: 20; PageSetup: Record=PageOptions¦CenterHorizontal=True¦CenterVertical=True¦PrintScale=0.97¦XCorrection=1.00¦YCorrection=1.00¦PrintKind=0¦BorderSize=5000000¦LeftOffset=0¦BottomOffset=0¦Orientation=2¦PaperLength=1000¦PaperWidth=1000¦Scale=100¦PaperSource=15¦PrintQuality=600¦MediaType=1¦DitherType=10¦PaperKind=Letter¦PrintScaleMode=1
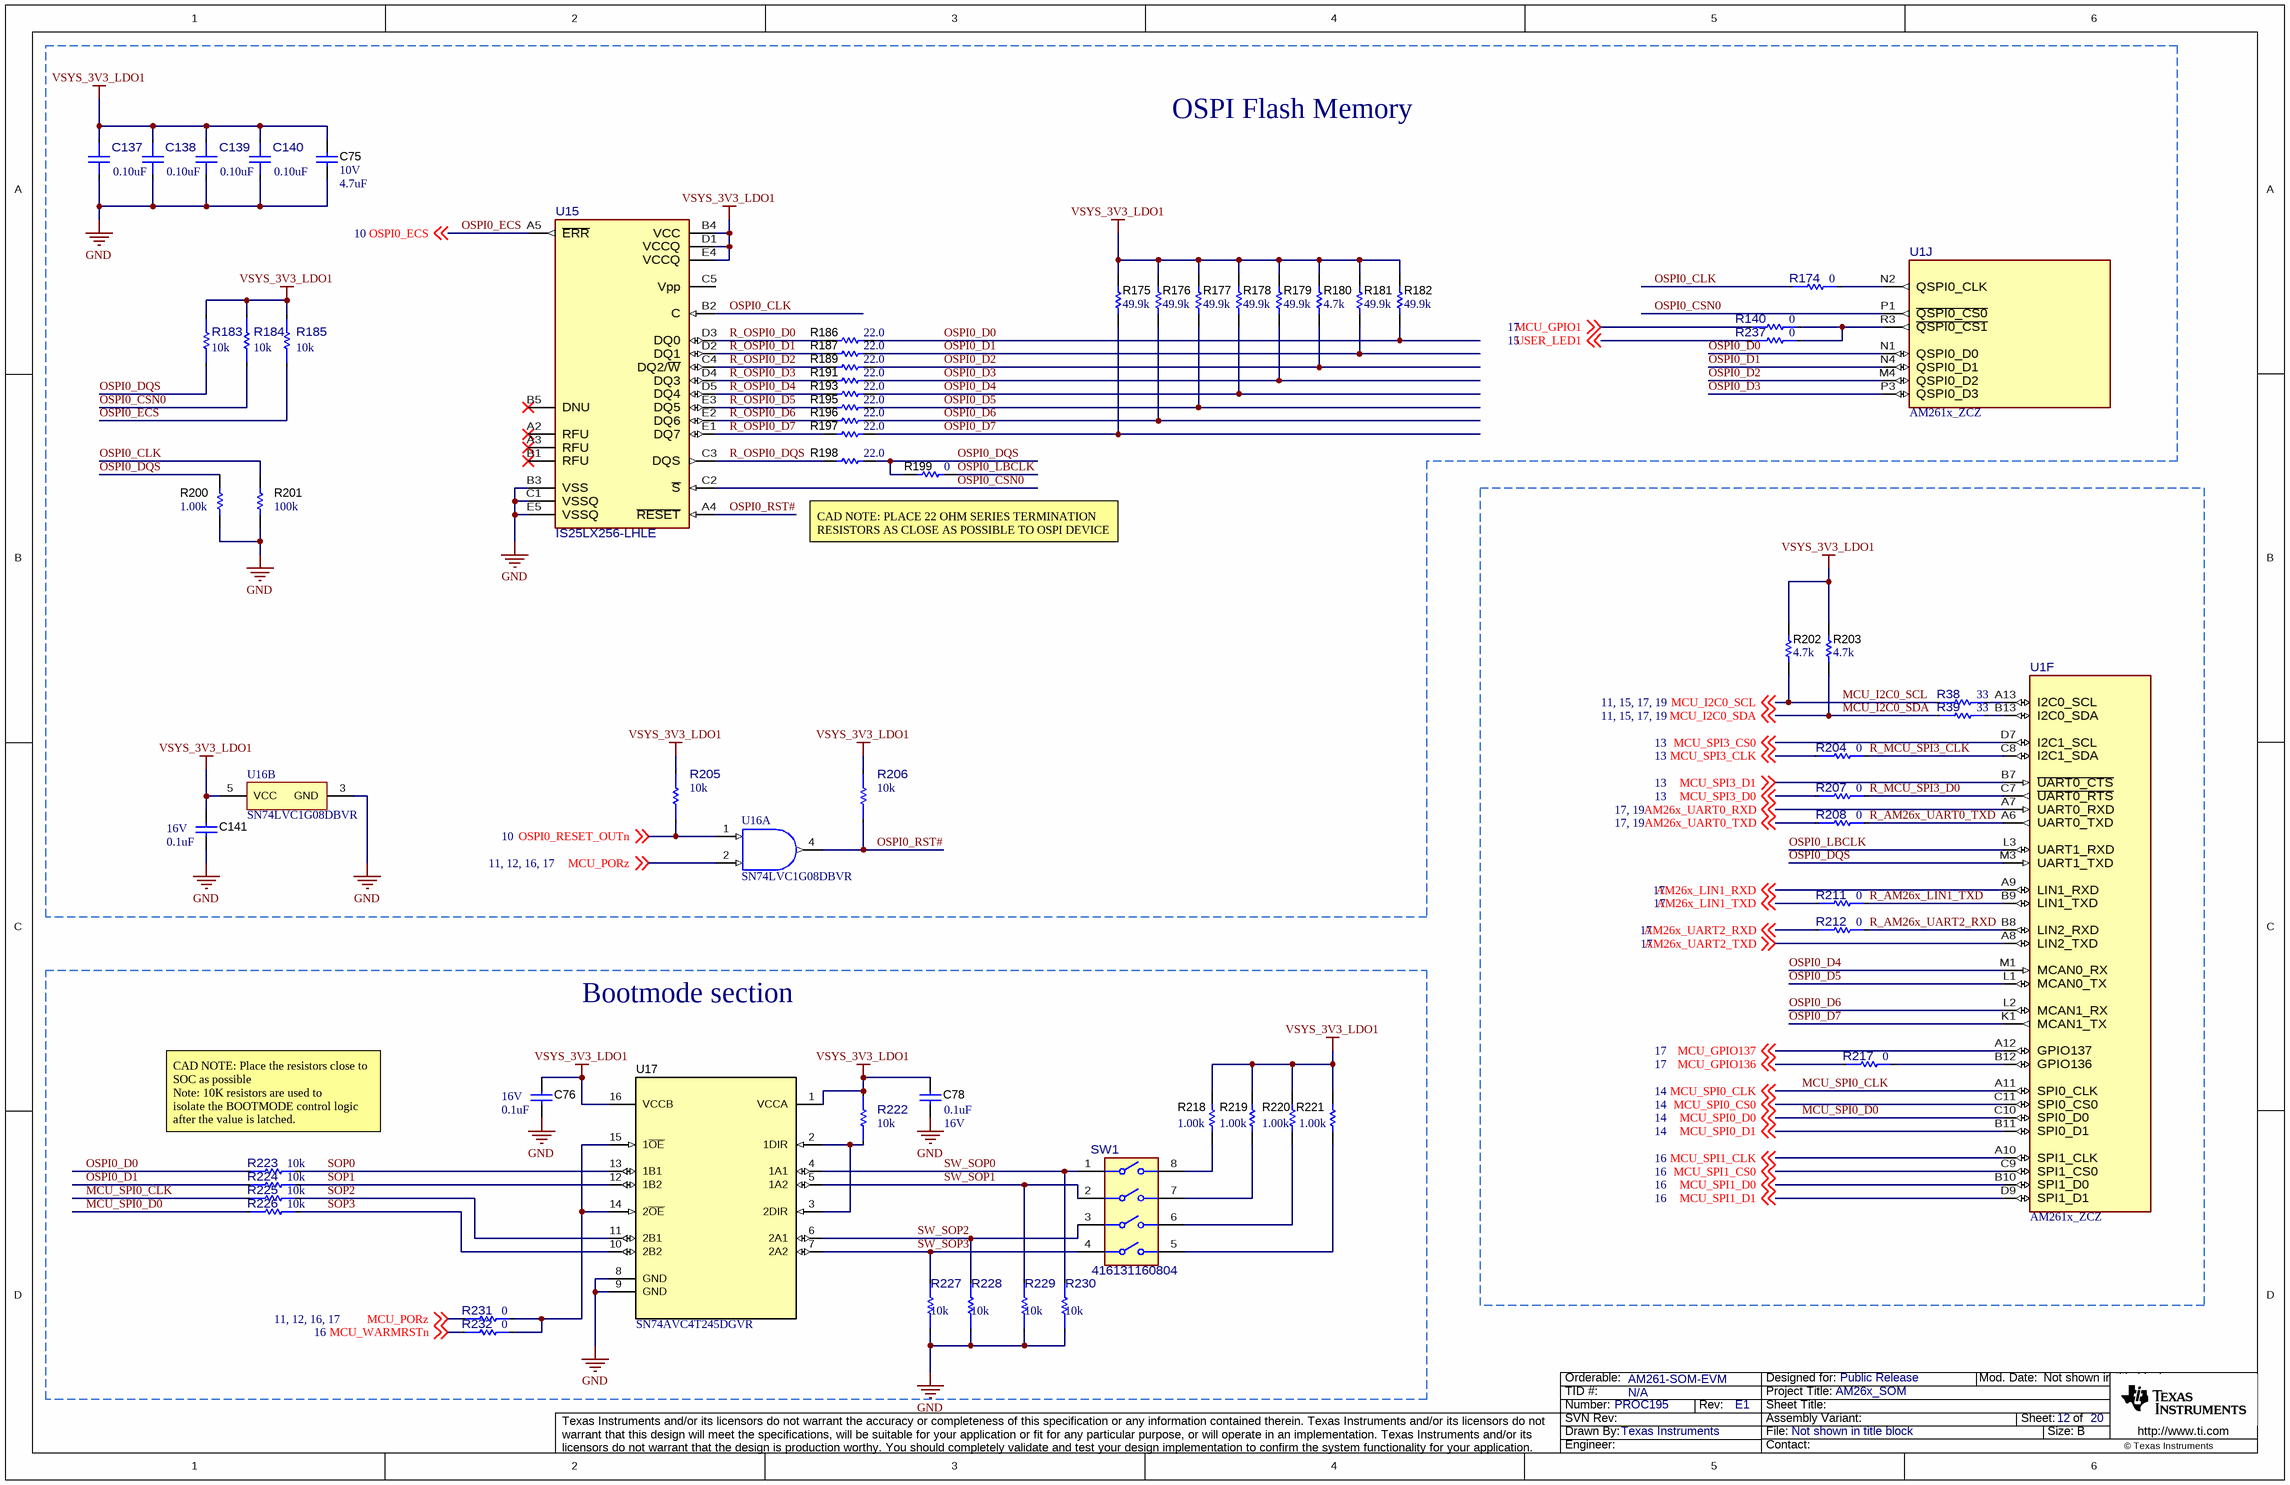
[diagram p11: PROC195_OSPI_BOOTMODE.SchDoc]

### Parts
C75  VDC_V: 10V  ValueDisplayed: 4.7uF  [0402]  (hidden comment: GRM155R61A475MEAAD)
C76  VDC_V: 16V  ValueDisplayed: 0.1uF  [0201]  (hidden comment: GRM033Z71C104KE14D)
C78  VDC_V: 16V  ValueDisplayed: 0.1uF  [0201]  (hidden comment: GRM033Z71C104KE14D)
C137  ValueDisplayed: 0.10uF  [FP-GRM155R71H104KE14D_0402-MFG]  (hidden comment: GRM155R71H104KE14D)
C138  ValueDisplayed: 0.10uF  [FP-GRM155R71H104KE14D_0402-MFG]  (hidden comment: GRM155R71H104KE14D)
C139  ValueDisplayed: 0.10uF  [FP-GRM155R71H104KE14D_0402-MFG]  (hidden comment: GRM155R71H104KE14D)
C140  ValueDisplayed: 0.10uF  [FP-GRM155R71H104KE14D_0402-MFG]  (hidden comment: GRM155R71H104KE14D)
C141  VDC_V: 16V  ValueDisplayed: 0.1uF  [0201]  (hidden comment: GRM033Z71C104KE14D)
R38  value 33  [FP-ERJ-2GEJ330X_0402-MFG]  (hidden comment: ERJ-2GEJ330X)
R39  value 33  [FP-ERJ-2GEJ330X_0402-MFG]  (hidden comment: ERJ-2GEJ330X)
R140  value 0  [FP-ERJ-2GE0R00X_0402-MFG]  (hidden comment: ERJ-2GE0R00X)
R174  value 0  [FP-ERJ-2GE0R00X_0402-MFG]  (hidden comment: ERJ-2GE0R00X)
R175  ValueDisplayed: 49.9k  [0201]  (hidden comment: RC0201FR-0749K9L)
R176  ValueDisplayed: 49.9k  [0201]  (hidden comment: RC0201FR-0749K9L)
R177  ValueDisplayed: 49.9k  [0201]  (hidden comment: RC0201FR-0749K9L)
R178  ValueDisplayed: 49.9k  [0201]  (hidden comment: RC0201FR-0749K9L)
R179  ValueDisplayed: 49.9k  [0201]  (hidden comment: RC0201FR-0749K9L)
R180  ValueDisplayed: 4.7k  [0402]  (hidden comment: CRCW04024K70JNED)
R181  ValueDisplayed: 49.9k  [0201]  (hidden comment: RC0201FR-0749K9L)
R182  ValueDisplayed: 49.9k  [0201]  (hidden comment: RC0201FR-0749K9L)
R183  value 10k  [FP-RC0402JR-0710KL_0402-MFG]  (hidden comment: RC0402JR-0710KL)
R184  value 10k  [FP-RC0402JR-0710KL_0402-MFG]  (hidden comment: RC0402JR-0710KL)
R185  value 10k  [FP-RC0402JR-0710KL_0402-MFG]  (hidden comment: RC0402JR-0710KL)
R186  ValueDisplayed: 22.0  [0201]  (hidden comment: RC0201FR-0722RL)
R187  ValueDisplayed: 22.0  [0201]  (hidden comment: RC0201FR-0722RL)
R189  ValueDisplayed: 22.0  [0201]  (hidden comment: RC0201FR-0722RL)
R191  ValueDisplayed: 22.0  [0201]  (hidden comment: RC0201FR-0722RL)
R193  ValueDisplayed: 22.0  [0201]  (hidden comment: RC0201FR-0722RL)
R195  ValueDisplayed: 22.0  [0201]  (hidden comment: RC0201FR-0722RL)
R196  ValueDisplayed: 22.0  [0201]  (hidden comment: RC0201FR-0722RL)
R197  ValueDisplayed: 22.0  [0201]  (hidden comment: RC0201FR-0722RL)
R198  ValueDisplayed: 22.0  [0201]  (hidden comment: RC0201FR-0722RL)
R199  ValueDisplayed: 0  [0201]  (hidden comment: ERJ-1GN0R00C)
R200  ValueDisplayed: 1.00k  [0402]  (hidden comment: ERJ-2RKF1001X)
R201  ValueDisplayed: 100k  [0402]  (hidden comment: CRCW0402100KJNED)
R202  ValueDisplayed: 4.7k  [0402]  (hidden comment: CRCW04024K70JNED)
R203  ValueDisplayed: 4.7k  [0402]  (hidden comment: CRCW04024K70JNED)
R204  value 0  [FP-ERJ-2GE0R00X_0402-MFG]  (hidden comment: ERJ-2GE0R00X)
R205  value 10k  [FP-RC0402JR-0710KL_0402-MFG]  (hidden comment: RC0402JR-0710KL)
R206  value 10k  [FP-RC0402JR-0710KL_0402-MFG]  (hidden comment: RC0402JR-0710KL)
R207  value 0  [FP-ERJ-2GE0R00X_0402-MFG]  (hidden comment: ERJ-2GE0R00X)
R208  value 0  [FP-ERJ-2GE0R00X_0402-MFG]  (hidden comment: ERJ-2GE0R00X)
R211  value 0  [FP-ERJ-2GE0R00X_0402-MFG]  (hidden comment: ERJ-2GE0R00X)
R212  value 0  [FP-ERJ-2GE0R00X_0402-MFG]  (hidden comment: ERJ-2GE0R00X)
R217  value 0  [FP-ERJ-2GE0R00X_0402-MFG]  (hidden comment: ERJ-2GE0R00X)
R218  ValueDisplayed: 1.00k  [0402]  (hidden comment: ERJ-2RKF1001X)
R219  ValueDisplayed: 1.00k  [0402]  (hidden comment: ERJ-2RKF1001X)
R220  ValueDisplayed: 1.00k  [0402]  (hidden comment: ERJ-2RKF1001X)
R221  ValueDisplayed: 1.00k  [0402]  (hidden comment: ERJ-2RKF1001X)
R222  value 10k  [FP-RC0402JR-0710KL_0402-MFG]  (hidden comment: RC0402JR-0710KL)
R223  value 10k  [FP-RC0402JR-0710KL_0402-MFG]  (hidden comment: RC0402JR-0710KL)
R224  value 10k  [FP-RC0402JR-0710KL_0402-MFG]  (hidden comment: RC0402JR-0710KL)
R225  value 10k  [FP-RC0402JR-0710KL_0402-MFG]  (hidden comment: RC0402JR-0710KL)
R226  value 10k  [FP-RC0402JR-0710KL_0402-MFG]  (hidden comment: RC0402JR-0710KL)
R227  value 10k  [FP-RC0402JR-0710KL_0402-MFG]  (hidden comment: RC0402JR-0710KL)
R228  value 10k  [FP-RC0402JR-0710KL_0402-MFG]  (hidden comment: RC0402JR-0710KL)
R229  value 10k  [FP-RC0402JR-0710KL_0402-MFG]  (hidden comment: RC0402JR-0710KL)
R230  value 10k  [FP-RC0402JR-0710KL_0402-MFG]  (hidden comment: RC0402JR-0710KL)
R231  value 0  [FP-ERJ-2GE0R00X_0402-MFG]  (hidden comment: ERJ-2GE0R00X)
R232  value 0  [FP-ERJ-2GE0R00X_0402-MFG]  (hidden comment: ERJ-2GE0R00X)
R237  value 0  [FP-ERJ-2GE0R00X_0402-MFG]  (hidden comment: ERJ-2GE0R00X)
SW1  416131160804  [FP-416131160804_SMT_SW-MFG]
U1  AM261x_ZCZ  [ZCZ0324A-MFG]  (parts F,J of 13)
U15  IS25LX256-LHLE  [FP-IS25LX256-LHLE_TFBGA24-IPC_C]
U16  SN74LVC1G08DBVR  [DBV0005A_N]  (parts A,B of 2)
U17  SN74AVC4T245DGVR  [DGV0016A_N]

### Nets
GND: C75.1 C76.2 C78.2 C137.2 C138.2 C139.2 C140.2 C141.2 R200.1 R201.1 R227.1 R228.1 R229.1 R230.1 U15.B3(VSS) U15.C1(VSSQ) U15.E5(VSSQ) U16.3(GND) U17.8(GND) U17.9(GND)
VSYS_3V3_LDO1: C75.2 C76.1 C78.1 C137.1 C138.1 C139.1 C140.1 C141.1 R175.2 R176.2 R177.2 R178.2 R179.2 R180.2 R181.2 R182.2 R183.2 R184.1 R185.2 R202.2 R203.2 R205.2 R206.2 R218.2 R219.2 R220.2 R221.2 R222.2 U15.B4(VCC) U15.D1(VCCQ) U15.E4(VCCQ) U16.5(VCC) U17.1(VCCA) U17.16(VCCB)
AM26x_LIN1_RXD: U1.A9(LIN1_RXD) ; off-sheet AM26x_LIN1_RXD
AM26x_LIN1_TXD: R211.1 ; off-sheet AM26x_LIN1_TXD
AM26x_UART0_RXD: U1.A7(UART0_RXD) ; off-sheet AM26x_UART0_RXD
AM26x_UART0_TXD: R208.1 ; off-sheet AM26x_UART0_TXD
AM26x_UART2_RXD: R212.1 ; off-sheet AM26x_UART2_RXD
AM26x_UART2_TXD: U1.A8(LIN2_TXD) ; off-sheet AM26x_UART2_TXD
MCU_GPIO1: R140.1 ; off-sheet MCU_GPIO1
MCU_GPIO136: R217.1 ; off-sheet MCU_GPIO136
MCU_GPIO137: U1.A12(GPIO137) ; off-sheet MCU_GPIO137
MCU_I2C0_SCL: R38.1 R202.1 ; off-sheet MCU_I2C0_SCL
MCU_I2C0_SDA: R39.1 R203.1 ; off-sheet MCU_I2C0_SDA
MCU_PORz: R231.1 U16.2(B) ; off-sheet MCU_PORz
MCU_SPI0_CLK: R225.1 U1.A11(SPI0_CLK) ; off-sheet MCU_SPI0_CLK
MCU_SPI0_CS0: U1.C11(SPI0_CS0) ; off-sheet MCU_SPI0_CS0
MCU_SPI0_D0: R226.1 U1.C10(SPI0_D0) ; off-sheet MCU_SPI0_D0
MCU_SPI0_D1: U1.B11(SPI0_D1) ; off-sheet MCU_SPI0_D1
MCU_SPI1_CLK: U1.A10(SPI1_CLK) ; off-sheet MCU_SPI1_CLK
MCU_SPI1_CS0: U1.C9(SPI1_CS0) ; off-sheet MCU_SPI1_CS0
MCU_SPI1_D0: U1.B10(SPI1_D0) ; off-sheet MCU_SPI1_D0
MCU_SPI1_D1: U1.D9(SPI1_D1) ; off-sheet MCU_SPI1_D1
MCU_SPI3_CLK: R204.1 ; off-sheet MCU_SPI3_CLK
MCU_SPI3_CS0: U1.D7(I2C1_SCL) ; off-sheet MCU_SPI3_CS0
MCU_SPI3_D0: R207.1 ; off-sheet MCU_SPI3_D0
MCU_SPI3_D1: U1.B7(~{UART0_CTS}) ; off-sheet MCU_SPI3_D1
MCU_WARMRSTn: R232.1 ; off-sheet MCU_WARMRSTn  [project net MCU_RESETn]
OSPI0_CLK: R174.1 R201.2 U15.B2(C)
OSPI0_CSN0: R184.2 U1.P1(~{QSPI0_CS0}) U15.C2(~{S})
OSPI0_D0: R182.1 R186.2 R223.1 U1.N1(QSPI0_D0)
OSPI0_D1: R181.1 R187.2 R224.1 U1.N4(QSPI0_D1)
OSPI0_D2: R180.1 R189.2 U1.M4(QSPI0_D2)
OSPI0_D3: R179.1 R191.2 U1.P3(QSPI0_D3)
OSPI0_D4: R178.1 R193.2 U1.M1(MCAN0_RX)
OSPI0_D5: R177.1 R195.2 U1.L1(MCAN0_TX)
OSPI0_D6: R176.1 R196.2 U1.L2(MCAN1_RX)
OSPI0_D7: R175.1 R197.2 U1.K1(MCAN1_TX)
OSPI0_DQS: R183.1 R198.2 R199.1 R200.2 U1.M3(UART1_TXD)
OSPI0_ECS: R185.1 U15.A5(~{ERR}) ; off-sheet OSPI0_ECS
OSPI0_LBCLK: R199.2 U1.L3(UART1_RXD)
OSPI0_RESET_OUTn: R205.1 U16.1(A) ; off-sheet OSPI0_RESET_OUTn
OSPI0_RST#: R206.1 U15.A4(~{RESET}) U16.4(Y)
R_AM26x_LIN1_TXD: R211.2 U1.B9(LIN1_TXD)
R_AM26x_UART0_TXD: R208.2 U1.A6(UART0_TXD)
R_AM26x_UART2_RXD: R212.2 U1.B8(LIN2_RXD)
R_MCU_SPI3_CLK: R204.2 U1.C8(I2C1_SDA)
R_MCU_SPI3_D0: R207.2 U1.C7(~{UART0_RTS})
R_OSPI0_D0: R186.1 U15.D3(DQ0)
R_OSPI0_D1: R187.1 U15.D2(DQ1)
R_OSPI0_D2: R189.1 U15.C4(DQ2/~{W})
R_OSPI0_D3: R191.1 U15.D4(DQ3)
R_OSPI0_D4: R193.1 U15.D5(DQ4)
R_OSPI0_D5: R195.1 U15.E3(DQ5)
R_OSPI0_D6: R196.1 U15.E2(DQ6)
R_OSPI0_D7: R197.1 U15.E1(DQ7)
R_OSPI0_DQS: R198.1 U15.C3(DQS)
SOP0: R223.2 U17.13(1B1)
SOP1: R224.2 U17.12(1B2)
SOP2: R225.2 U17.11(2B1)
SOP3: R226.2 U17.10(2B2)
SW_SOP0: R230.2 SW1.1 U17.4(1A1)
SW_SOP1: R229.2 SW1.2 U17.5(1A2)
SW_SOP2: R228.2 SW1.3 U17.6(2A1)
SW_SOP3: R227.2 SW1.4 U17.7(2A2)
USER_LED1: R237.1 ; off-sheet USER_LED1
NetR38_2: R38.2 U1.A13(I2C0_SCL)
NetR39_2: R39.2 U1.B13(I2C0_SDA)
NetR140_2: R140.2 R237.2 U1.R3(~{QSPI0_CS1})
NetR174_2: R174.2 U1.N2(QSPI0_CLK)
NetR217_2: R217.2 U1.B12(GPIO136)
NetR218_1: R218.1 SW1.8
NetR219_1: R219.1 SW1.7
NetR220_1: R220.1 SW1.6
NetR221_1: R221.1 SW1.5
NetR222_1: R222.1 U17.2(1DIR) U17.3(2DIR)
NetR231_2: R231.2 R232.2 U17.14(2~{OE}) U17.15(1~{OE})

Not connected (* = marked no-connect by the designer): U15 A2(RFU)* A3(RFU)* B1(RFU)* B5(DNU)* C5(Vpp)

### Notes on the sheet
- OSPI Flash Memory
- CAD NOTE: PLACE 22 OHM SERIES TERMINATION RESISTORS AS CLOSE AS POSSIBLE TO OSPI DEVICE
- Bootmode section
- CAD NOTE: Place the resistors close to SOC as possible
  Note: 10K resistors are used to
  isolate the BOOTMODE control logic
  after the value is latched.

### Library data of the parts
C75 = CMP-0006582-2: CAP, CERM, 4.7 uF, 10 V, +/- 20%, X5R, 0402; Manufacturer: MuRata; TaMin_C: -55°C; Polarized: N; SizeAreaWB_mm2: 3; Value1: Unknown; U/M: EA; Value: 4.7uF; TaMax_C: 85°C; SizeZ_mm: 0.6; SizeX_mm: 1; SizeY_mm: 0.5; Cap_F: 4.7µF; AEC Category: Q200
C76 C78 C141 = CMP-0064970-1: as C131 on sheet PROC195_SDFM, JTAG
C137-C140 = CMP-0096855-1: as C174 on sheet PROC195_SDFM, JTAG
R38 R39 = CMP-0122104-1: 33 Ohms ±5% 0.1W, 1/10W Chip Resistor 0402 (1005 Metric) Automotive AEC-Q200 Thick Film; Manufacturer: Panasonic; AEC Grade: Grade 0; AEC Qualified: Yes; Power_W: 100mW; SizeZ_mm: 0.4mm; TempCo: 200ppm/°C; VDC_V: 50V
R140 R174 R204 R207 R208 R211 R212 R217 R231 R232 R237 = CMP-0002710-1: as R76 on sheet PROC195_SDFM, JTAG
R175-R179 R181 R182 = CMP-0027732-1: RES, 49.9 k, 1%, 0.05 W, 0201; Manufacturer: Yageo America; Power_W: 50mW; TempCo: 200 ppm/C; Value_Code: 49k9; U/M: EA; Value: 49.9k; EIA_Code: E96; SizeX_mm: 0.6; SizeY_mm: 0.3; SizeZ_mm: 0.26; Value2: 0.05W; SizeArea_mm2: 0.18; AEC Qualified: N; VDC_V: 25V; AEC Category: Q200
R180 R202 R203 = CMP-0026938-5: as R157 on sheet PROC195_SDFM, JTAG
R183-R185 R205 R206 R222-R230 = CMP-0094798-1: as R80 on sheet PROC195_SDFM, JTAG
R186 R187 R189 R191 R193 R195-R198 = CMP-0027500-1: as R106 on sheet PROC195_EPWM
R199 = CMP-0065361-1: as R4 on sheet PROC195_EPWM
R200 R218-R221 = CMP-0026657-1: RES, 1.00 k, 1%, 0.1 W, 0402; Manufacturer: Panasonic; Value_Code: 1k00; SizeArea_mm2: 0.5; AEC Category: Q200; Res_ohm: 1k; Value: 1.00k; SizeZ_mm: 0.6; EIA_Code: E96; TempCo: 100 ppm/C; Power_W: 100mW; VDC_V: 50V; Value2: 0.1W; U/M: EA; SizeX_mm: 1
R201 = CMP-0026823-3: RES, 100 k, 5%, 0.063 W, AEC-Q200 Grade 0, 0402; Manufacturer: Vishay-Dale; Value2: 0.063W; EIA_Code: E24; Value: 100k; SizeArea_mm2: 0.5; TempCo: 200 ppm/C; SizeZ_mm: 0.6; AEC Category: Q200; VDC_V: 50V; Power_W: 63mW; AEC Grade: 0; SizeX_mm: 1; AEC Qualified: Y
SW1 = CMP-0093176-1: Dip Switch SPST 4 Position Surface Mount Slide (Standard) Actuator 25mA 24VDC; Manufacturer: Wurth; PositionCount: 4; Electromechanical Life: 1000Cycles; Circuit: 4PST; Coil Resistance_ohm: 100mΩ; VDC_V: 24V; Standoff Height: 0mm; SizeZ_mm: 2.65mm; AEC Qualified: No
U1 = CMP-0121930-1: as U1 on sheet PROC195_EPWM
U15 = CMP-0120691-1: FLASH Memory IC 256Mbit SPI - Octal I/O 133 MHz 6 ns 24-TFBGA (6x8); Manufacturer: ISSI; SizeZ_mm: 1.2mm; Access Time: 6ns; AEC Qualified: No; Frequency_Fixed: 133MHz; Max Supply Voltage: 3.6V; Min Supply Voltage: 2.7V; Nominal Supply Current: 0.13-48mA; Standoff Height: 0.26mm; TaMax_C: +105°C; TaMin_C: -40°C
U16 = CMP-0051588-2: Single 2-Input Positive-AND Gate, DBV0005A, LARGE T&R; Manufacturer: Texas Instruments; Logic: True; ICC @ Nom Voltage(Max)(mA): 0.01; VCC(Min)(V): 1.65; Bits(#): 1; Rating: Catalog; Schmitt Trigger: No; Voltage(Nom)(V): 1.8,2.5,3.3,5; Output Drive (IOL/IOH)(Max)(mA): 32/-32; Gate Type: AND; tpd @ Nom Voltage(Max)(ns): 4.5,6,4,5; VCC(Max)(V): 5.5; Output Type: CMOS; F @ Nom Voltage(Max)(Mhz): 150; Input Type: CMOS/TTL; Technology Family: LVC; AEC Category: Q200; AEC Qualified: N; CompType: IC
U17 = CMP-0066446-2: 4-Bit Dual-Supply Bus Transceiver with Configurable Voltage-Level Shifting and 3-State Outputs, DGV0016A (TVSOP-16); Alternate Manufacturer: Texas Instruments; Green_Lifecycle: Active; SizeAreaWB_mm2: 70.56; Green_REACh: Passed; SizeZ_mm: 1.2; SizeX_mm: 6.4; SizeArea_mm2: 40.96; CompType: IC; AEC Category: Q200; AEC Qualified: N

## Sheet PROC195_ADC.SchDoc
size 431 x 279 mm; ENG_APP_DATE: --/--/--; DSN_APP_DATE: --/--/--; CHK_APP_DATE: --/--/--; Date: Not shown in title block; ApprovedBy: Not shown in title block; CheckedBy: Not shown in title block; Author: Not shown in title block; CompanyName: Not shown in title block; Engineer: Not shown in title block; Organization: Not shown in title block; Address1: Not shown in title block; Address2: Not shown in title block; Address3: Not shown in title block; Address4: Not shown in title block; DocumentNumber: 1; Revision: Use project parameter SCH_Rev; SheetNumber: 13; SheetTotal: 20; PageSetup: Record=PageOptions¦CenterHorizontal=True¦CenterVertical=True¦PrintScale=1.00¦XCorrection=1.00¦YCorrection=1.00¦PrintKind=0¦BorderSize=5000000¦LeftOffset=0¦BottomOffset=0¦Orientation=2¦PaperLength=1000¦PaperWidth=1000¦Scale=100¦PaperSource=15¦PrintQuality=600¦MediaType=1¦DitherType=10¦PaperKind=Letter¦PrintScaleMode=1
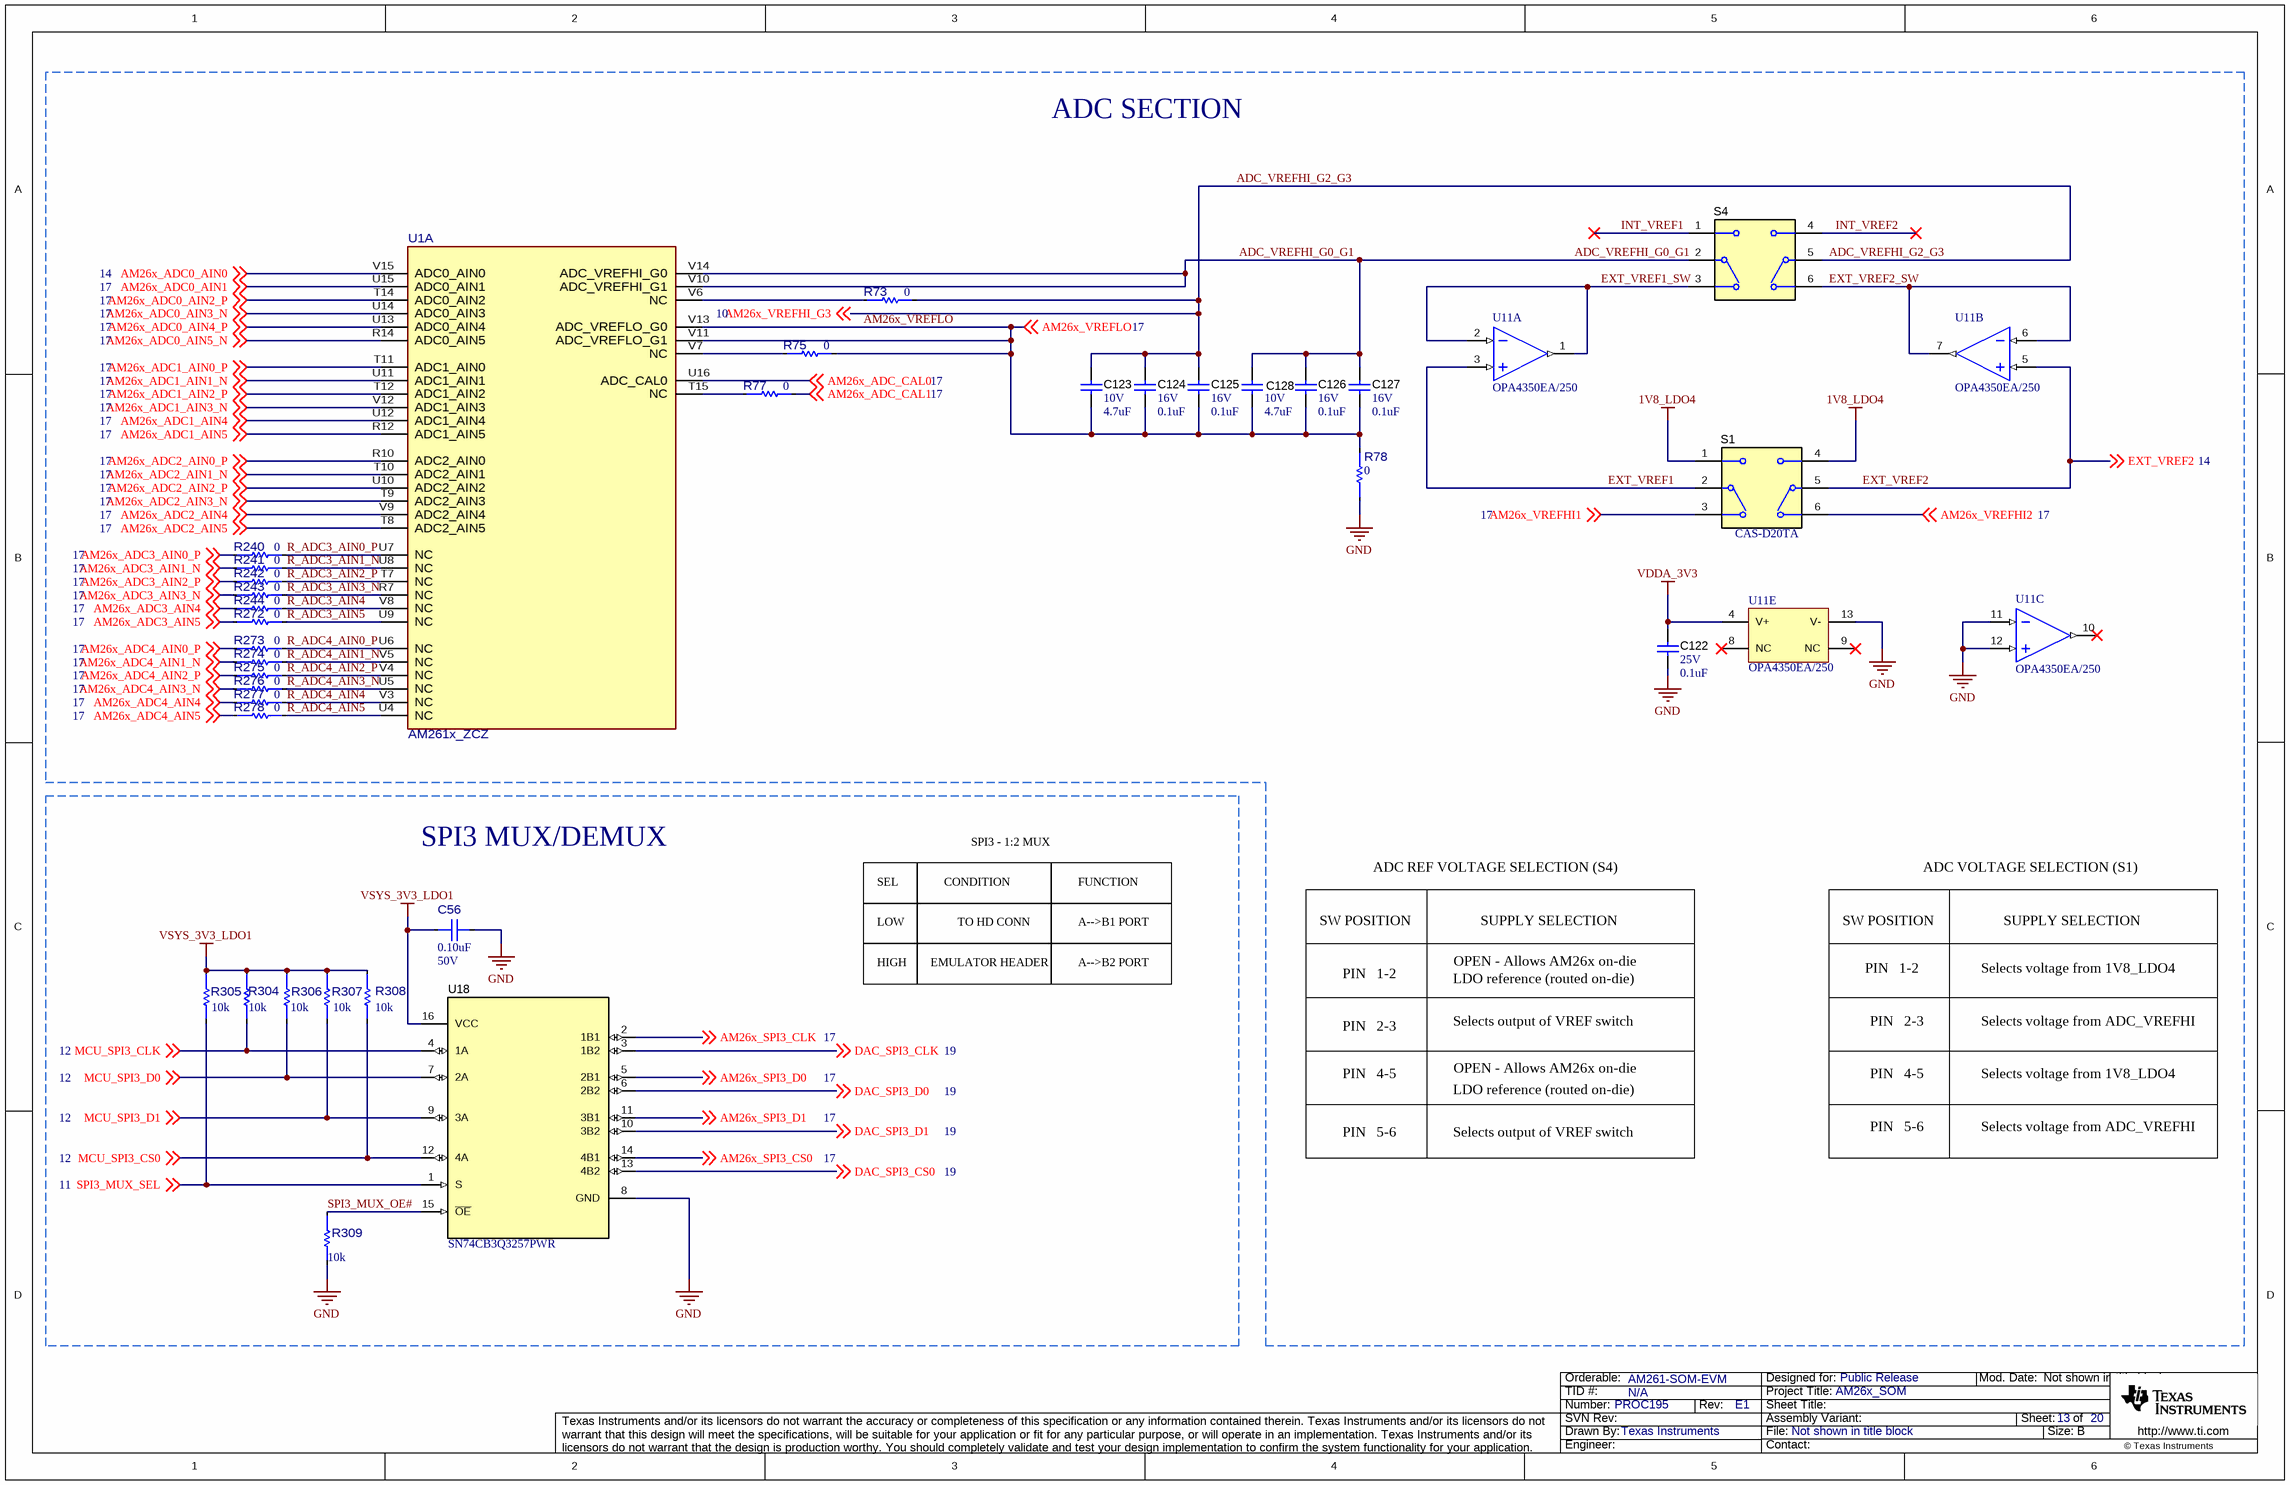
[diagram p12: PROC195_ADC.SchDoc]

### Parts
C56  ValueDisplayed: 0.10uF  VDC_V: 50V  [FP-GRM155R71H104KE14D_0402-MFG]  (hidden comment: GRM155R71H104KE14D)
C122  VDC_V: 25V  ValueDisplayed: 0.1uF  [0402]  (hidden comment: GRM155R71E104KE14D)
C123  VDC_V: 10V  ValueDisplayed: 4.7uF  [0402]  (hidden comment: GRM155R61A475MEAAD)
C124  VDC_V: 16V  ValueDisplayed: 0.1uF  [0201]  (hidden comment: GRM033Z71C104KE14D)
C125  VDC_V: 16V  ValueDisplayed: 0.1uF  [0201]  (hidden comment: GRM033Z71C104KE14D)
C126  VDC_V: 16V  ValueDisplayed: 0.1uF  [0201]  (hidden comment: GRM033Z71C104KE14D)
C127  VDC_V: 16V  ValueDisplayed: 0.1uF  [0201]  (hidden comment: GRM033Z71C104KE14D)
C128  VDC_V: 10V  ValueDisplayed: 4.7uF  [0402]  (hidden comment: GRM155R61A475MEAAD)
R73  value 0  [FP-ERJ-2GE0R00X_0402-MFG]  (hidden comment: ERJ-2GE0R00X)
R75  value 0  [FP-ERJ-2GE0R00X_0402-MFG]  (hidden comment: ERJ-2GE0R00X)
R77  value 0  [FP-ERJ-2GE0R00X_0402-MFG]  (hidden comment: ERJ-2GE0R00X)
R78  value 0  [FP-ERJ-2GE0R00X_0402-MFG]  (hidden comment: ERJ-2GE0R00X)
R240  value 0  [FP-ERJ-2GE0R00X_0402-MFG]  (hidden comment: ERJ-2GE0R00X)
R241  value 0  [FP-ERJ-2GE0R00X_0402-MFG]  (hidden comment: ERJ-2GE0R00X)
R242  value 0  [FP-ERJ-2GE0R00X_0402-MFG]  (hidden comment: ERJ-2GE0R00X)
R243  value 0  [FP-ERJ-2GE0R00X_0402-MFG]  (hidden comment: ERJ-2GE0R00X)
R244  value 0  [FP-ERJ-2GE0R00X_0402-MFG]  (hidden comment: ERJ-2GE0R00X)
R272  value 0  [FP-ERJ-2GE0R00X_0402-MFG]  (hidden comment: ERJ-2GE0R00X)
R273  value 0  [FP-ERJ-2GE0R00X_0402-MFG]  (hidden comment: ERJ-2GE0R00X)
R274  value 0  [FP-ERJ-2GE0R00X_0402-MFG]  (hidden comment: ERJ-2GE0R00X)
R275  value 0  [FP-ERJ-2GE0R00X_0402-MFG]  (hidden comment: ERJ-2GE0R00X)
R276  value 0  [FP-ERJ-2GE0R00X_0402-MFG]  (hidden comment: ERJ-2GE0R00X)
R277  value 0  [FP-ERJ-2GE0R00X_0402-MFG]  (hidden comment: ERJ-2GE0R00X)
R278  value 0  [FP-ERJ-2GE0R00X_0402-MFG]  (hidden comment: ERJ-2GE0R00X)
R304  value 10k  [FP-RC0402JR-0710KL_0402-MFG]  (hidden comment: RC0402JR-0710KL)
R305  value 10k  [FP-RC0402JR-0710KL_0402-MFG]  (hidden comment: RC0402JR-0710KL)
R306  value 10k  [FP-RC0402JR-0710KL_0402-MFG]  (hidden comment: RC0402JR-0710KL)
R307  value 10k  [FP-RC0402JR-0710KL_0402-MFG]  (hidden comment: RC0402JR-0710KL)
R308  value 10k  [FP-RC0402JR-0710KL_0402-MFG]  (hidden comment: RC0402JR-0710KL)
R309  value 10k  [FP-RC0402JR-0710KL_0402-MFG]  (hidden comment: RC0402JR-0710KL)
S1  CAS-D20TA  [SW_CAS-D20TA]
S4  CAS-D20TA  [SW_CAS-D20TA]  (value not drawn)
U1  AM261x_ZCZ  [ZCZ0324A-MFG]  (part A of 13)
U11  OPA4350EA/250  [DBQ0016A_N]  (parts A,B,C,E of 5)
U18  SN74CB3Q3257PWR  [PW0016A_L]

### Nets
1V8_LDO4: S1.1 S1.4
GND: C56.2 C122.1 R78.1 R309.2 U11.11(IN_C-) U11.12(IN_C+) U11.13(V-) U18.8(GND)
VDDA_3V3: C122.2 U11.4(V+)
VSYS_3V3_LDO1: C56.1 R304.1 R305.1 R306.1 R307.1 R308.1 U18.16(VCC)
ADC_VREFHI_G0_G1: C126.2 C127.2 C128.2 S4.2(C) U1.V10(ADC_VREFHI_G1) U1.V14(ADC_VREFHI_G0)
ADC_VREFHI_G2_G3: C123.2 C124.2 C125.2 R73.2 S4.5(C) ; off-sheet AM26x_VREFHI_G3  [also labelled AM26x_VREFHI_G3]
AM26x_ADC0_AIN0: U1.V15(ADC0_AIN0) ; off-sheet AM26x_ADC0_AIN0
AM26x_ADC0_AIN1: U1.U15(ADC0_AIN1) ; off-sheet AM26x_ADC0_AIN1
AM26x_ADC0_AIN2_P: U1.T14(ADC0_AIN2) ; off-sheet AM26x_ADC0_AIN2_P
AM26x_ADC0_AIN3_N: U1.U14(ADC0_AIN3) ; off-sheet AM26x_ADC0_AIN3_N
AM26x_ADC0_AIN4_P: U1.U13(ADC0_AIN4) ; off-sheet AM26x_ADC0_AIN4_P
AM26x_ADC0_AIN5_N: U1.R14(ADC0_AIN5) ; off-sheet AM26x_ADC0_AIN5_N
AM26x_ADC1_AIN0_P: U1.T11(ADC1_AIN0) ; off-sheet AM26x_ADC1_AIN0_P
AM26x_ADC1_AIN1_N: U1.U11(ADC1_AIN1) ; off-sheet AM26x_ADC1_AIN1_N
AM26x_ADC1_AIN2_P: U1.T12(ADC1_AIN2) ; off-sheet AM26x_ADC1_AIN2_P
AM26x_ADC1_AIN3_N: U1.V12(ADC1_AIN3) ; off-sheet AM26x_ADC1_AIN3_N
AM26x_ADC1_AIN4: U1.U12(ADC1_AIN4) ; off-sheet AM26x_ADC1_AIN4
AM26x_ADC1_AIN5: U1.R12(ADC1_AIN5) ; off-sheet AM26x_ADC1_AIN5
AM26x_ADC2_AIN0_P: U1.R10(ADC2_AIN0) ; off-sheet AM26x_ADC2_AIN0_P
AM26x_ADC2_AIN1_N: U1.T10(ADC2_AIN1) ; off-sheet AM26x_ADC2_AIN1_N
AM26x_ADC2_AIN2_P: U1.U10(ADC2_AIN2) ; off-sheet AM26x_ADC2_AIN2_P
AM26x_ADC2_AIN3_N: U1.T9(ADC2_AIN3) ; off-sheet AM26x_ADC2_AIN3_N
AM26x_ADC2_AIN4: U1.V9(ADC2_AIN4) ; off-sheet AM26x_ADC2_AIN4
AM26x_ADC2_AIN5: U1.T8(ADC2_AIN5) ; off-sheet AM26x_ADC2_AIN5
AM26x_ADC3_AIN0_P: R240.1 ; off-sheet AM26x_ADC3_AIN0_P
AM26x_ADC3_AIN1_N: R241.1 ; off-sheet AM26x_ADC3_AIN1_N
AM26x_ADC3_AIN2_P: R242.1 ; off-sheet AM26x_ADC3_AIN2_P
AM26x_ADC3_AIN3_N: R243.1 ; off-sheet AM26x_ADC3_AIN3_N
AM26x_ADC3_AIN4: R244.1 ; off-sheet AM26x_ADC3_AIN4
AM26x_ADC3_AIN5: R272.1 ; off-sheet AM26x_ADC3_AIN5
AM26x_ADC4_AIN0_P: R273.1 ; off-sheet AM26x_ADC4_AIN0_P
AM26x_ADC4_AIN1_N: R274.1 ; off-sheet AM26x_ADC4_AIN1_N
AM26x_ADC4_AIN2_P: R275.1 ; off-sheet AM26x_ADC4_AIN2_P
AM26x_ADC4_AIN3_N: R276.1 ; off-sheet AM26x_ADC4_AIN3_N
AM26x_ADC4_AIN4: R277.1 ; off-sheet AM26x_ADC4_AIN4
AM26x_ADC4_AIN5: R278.1 ; off-sheet AM26x_ADC4_AIN5
AM26x_ADC_CAL0: U1.U16(ADC_CAL0) ; off-sheet AM26x_ADC_CAL0
AM26x_ADC_CAL1: R77.2 ; off-sheet AM26x_ADC_CAL1
AM26x_SPI3_CLK: U18.2(1B1) ; off-sheet AM26x_SPI3_CLK
AM26x_SPI3_CS0: U18.14(4B1) ; off-sheet AM26x_SPI3_CS0
AM26x_SPI3_D0: U18.5(2B1) ; off-sheet AM26x_SPI3_D0
AM26x_SPI3_D1: U18.11(3B1) ; off-sheet AM26x_SPI3_D1
AM26x_VREFHI1: S1.3 ; off-sheet AM26x_VREFHI1
AM26x_VREFHI2: S1.6 ; off-sheet AM26x_VREFHI2
AM26x_VREFLO: C123.1 C124.1 C125.1 C126.1 C127.1 C128.1 R75.2 R78.2 U1.V11(ADC_VREFLO_G1) U1.V13(ADC_VREFLO_G0) ; off-sheet AM26x_VREFLO
DAC_SPI3_CLK: U18.3(1B2) ; off-sheet DAC_SPI3_CLK
DAC_SPI3_CS0: U18.13(4B2) ; off-sheet DAC_SPI3_CS0
DAC_SPI3_D0: U18.6(2B2) ; off-sheet DAC_SPI3_D0
DAC_SPI3_D1: U18.10(3B2) ; off-sheet DAC_SPI3_D1
EXT_VREF1: S1.2(C) U11.3(IN_A+)
EXT_VREF1_SW: S4.3 U11.1(OUT_A) U11.2(IN_A-)
EXT_VREF2: S1.5(C) U11.5(IN_B+) ; off-sheet EXT_VREF2
EXT_VREF2_SW: S4.6 U11.6(IN_B-) U11.7(OUT_B)
INT_VREF1: S4.1
INT_VREF2: S4.4
MCU_SPI3_CLK: R304.2 U18.4(1A) ; off-sheet MCU_SPI3_CLK
MCU_SPI3_CS0: R308.2 U18.12(4A) ; off-sheet MCU_SPI3_CS0
MCU_SPI3_D0: R306.2 U18.7(2A) ; off-sheet MCU_SPI3_D0
MCU_SPI3_D1: R307.2 U18.9(3A) ; off-sheet MCU_SPI3_D1
R_ADC3_AIN0_P: R240.2 U1.U7(NC)
R_ADC3_AIN1_N: R241.2 U1.U8(NC)
R_ADC3_AIN2_P: R242.2 U1.T7(NC)
R_ADC3_AIN3_N: R243.2 U1.R7(NC)
R_ADC3_AIN4: R244.2 U1.V8(NC)
R_ADC3_AIN5: R272.2 U1.U9(NC)
R_ADC4_AIN0_P: R273.2 U1.U6(NC)
R_ADC4_AIN1_N: R274.2 U1.V5(NC)
R_ADC4_AIN2_P: R275.2 U1.V4(NC)
R_ADC4_AIN3_N: R276.2 U1.U5(NC)
R_ADC4_AIN4: R277.2 U1.V3(NC)
R_ADC4_AIN5: R278.2 U1.U4(NC)
SPI3_MUX_OE#: R309.1 U18.15(~{OE})
SPI3_MUX_SEL: R305.2 U18.1(S) ; off-sheet SPI3_MUX_SEL
NetR73_1: R73.1 U1.V6(NC)
NetR75_1: R75.1 U1.V7(NC)
NetR77_1: R77.1 U1.T15(NC)

Not connected (* = marked no-connect by the designer): U11 8(NC)* 9(NC)* 10(OUT_C)*

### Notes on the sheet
- ADC SECTION
- Type @ to refer to a designator or a net
- SPI3 MUX/DEMUX
- SEL
- CONDITION
- SPI3 - 1:2 MUX
- FUNCTION
- ADC REF VOLTAGE SELECTION (S4)
- ADC VOLTAGE SELECTION (S1)
- LOW
- HIGH
- EMULATOR HEADER
- TO HD CONN
- A-->B1 PORT
- A-->B2 PORT
- SW POSITION
- OPEN - Allows AM26x on-die
- SUPPLY SELECTION
- PIN   1-2
- PIN   2-3
- Selects output of VREF switch
- LDO reference (routed on-die)
- Selects voltage from 1V8_LDO4
- Selects voltage from ADC_VREFHI
- PIN   4-5
- PIN   5-6

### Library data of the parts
C56 = CMP-0096855-1: as C174 on sheet PROC195_SDFM, JTAG
C122 = CMP-0006659-2: CAP, CERM, 0.1 uF, 25 V, +/- 10%, X7R, 0402; Manufacturer: MuRata; TaMin_C: -55°C; Polarized: N; SizeAreaWB_mm2: 3; Value1: Unknown; U/M: EA; Value: 0.1uF; TaMax_C: 125°C; SizeZ_mm: 0.6; SizeX_mm: 1; SizeY_mm: 0.5; Cap_F: 100nF; AEC Category: Q200
C123 C128 = CMP-0006582-2: as C75 on sheet PROC195_OSPI_BOOTMODE
C124-C127 = CMP-0064970-1: as C131 on sheet PROC195_SDFM, JTAG
R73 R75 R77 R78 R240-R244 R272-R278 = CMP-0002710-1: as R76 on sheet PROC195_SDFM, JTAG
R304-R309 = CMP-0094798-1: Res Thick Film 0402 10K Ohm 5% 0.063W(1/16W) ±100ppm/C Pad SMD T/R; Manufacturer: YAGEO; AEC Qualified: No; Category Cd01000Bfc2916C6: Single Components; SizeZ_mm: 0.4mm; VDC_V: 50V; Category 5C6A91606D4187Ad: Resistors; TempCo: 100ppm/°C; Power_W: 63mW; Category 7542B8484461Ae85: Passive Components
S1 S4 = CMP-0002233-1: Switch, Dual SPDT,  2 Pos, 0.1A, 6VDC, SMD; Manufacturer: Copal Electronics; CurrentRating_mA: 100A; SwitchFunction: On-On; VDC_V: 6V; PositionCount: 2
U1 = CMP-0121930-1: as U1 on sheet PROC195_EPWM
U11 = CMP-0041147-1: High-Speed, Single-Supply, Rail-to-Rail Operational Amplifier MicroAmplifier(TM) Series, 2.7 to 5.5 V, -55 to 150 degC, 16-pin SOP (DBQ16), Green (RoHS & no Sb/Br); Manufacturer: Texas Instruments; Number of Channels: 4; Vio (25C)(Max)(mV): 0.5; Total Supply Voltage(Min)(+5V is 5, +/-5V is 10): 2.7; Slew Rate(Typ)(V/us): 22; Total Supply Voltage(Max)(+5V is 5, +/-5V is 10): 5.5; Iq per channel(Max)(mA): 7.5; Vn at 1kHz(Typ)(nV/rtHz): 18; Sub Family: Low Input Bias Current Amp (<=10pA), Low Offset Voltage Amplifier (<=500uV), Low Supply Voltage Amplifier (<=2.7V), Precision Amplifier; IIB(Max)(pA): 10; CMRR(Min)(dB): 66
U18 = CMP-0076540-1: 4-Bit One-of-2 FET Multiplexer/Demultiplexer 2.5-V/3.3-V Low-Voltage, High-Bandwidth Bus Switch, PW0016A (TSSOP-16); Manufacturer: Texas Instruments; SizeAreaWB_mm2: 58.8; SizeArea_mm2: 32.0; SizeZ_mm: 1.2; SizeY_mm: 5.0; U/M: EA; CompType: IC; SizeX_mm: 6.4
